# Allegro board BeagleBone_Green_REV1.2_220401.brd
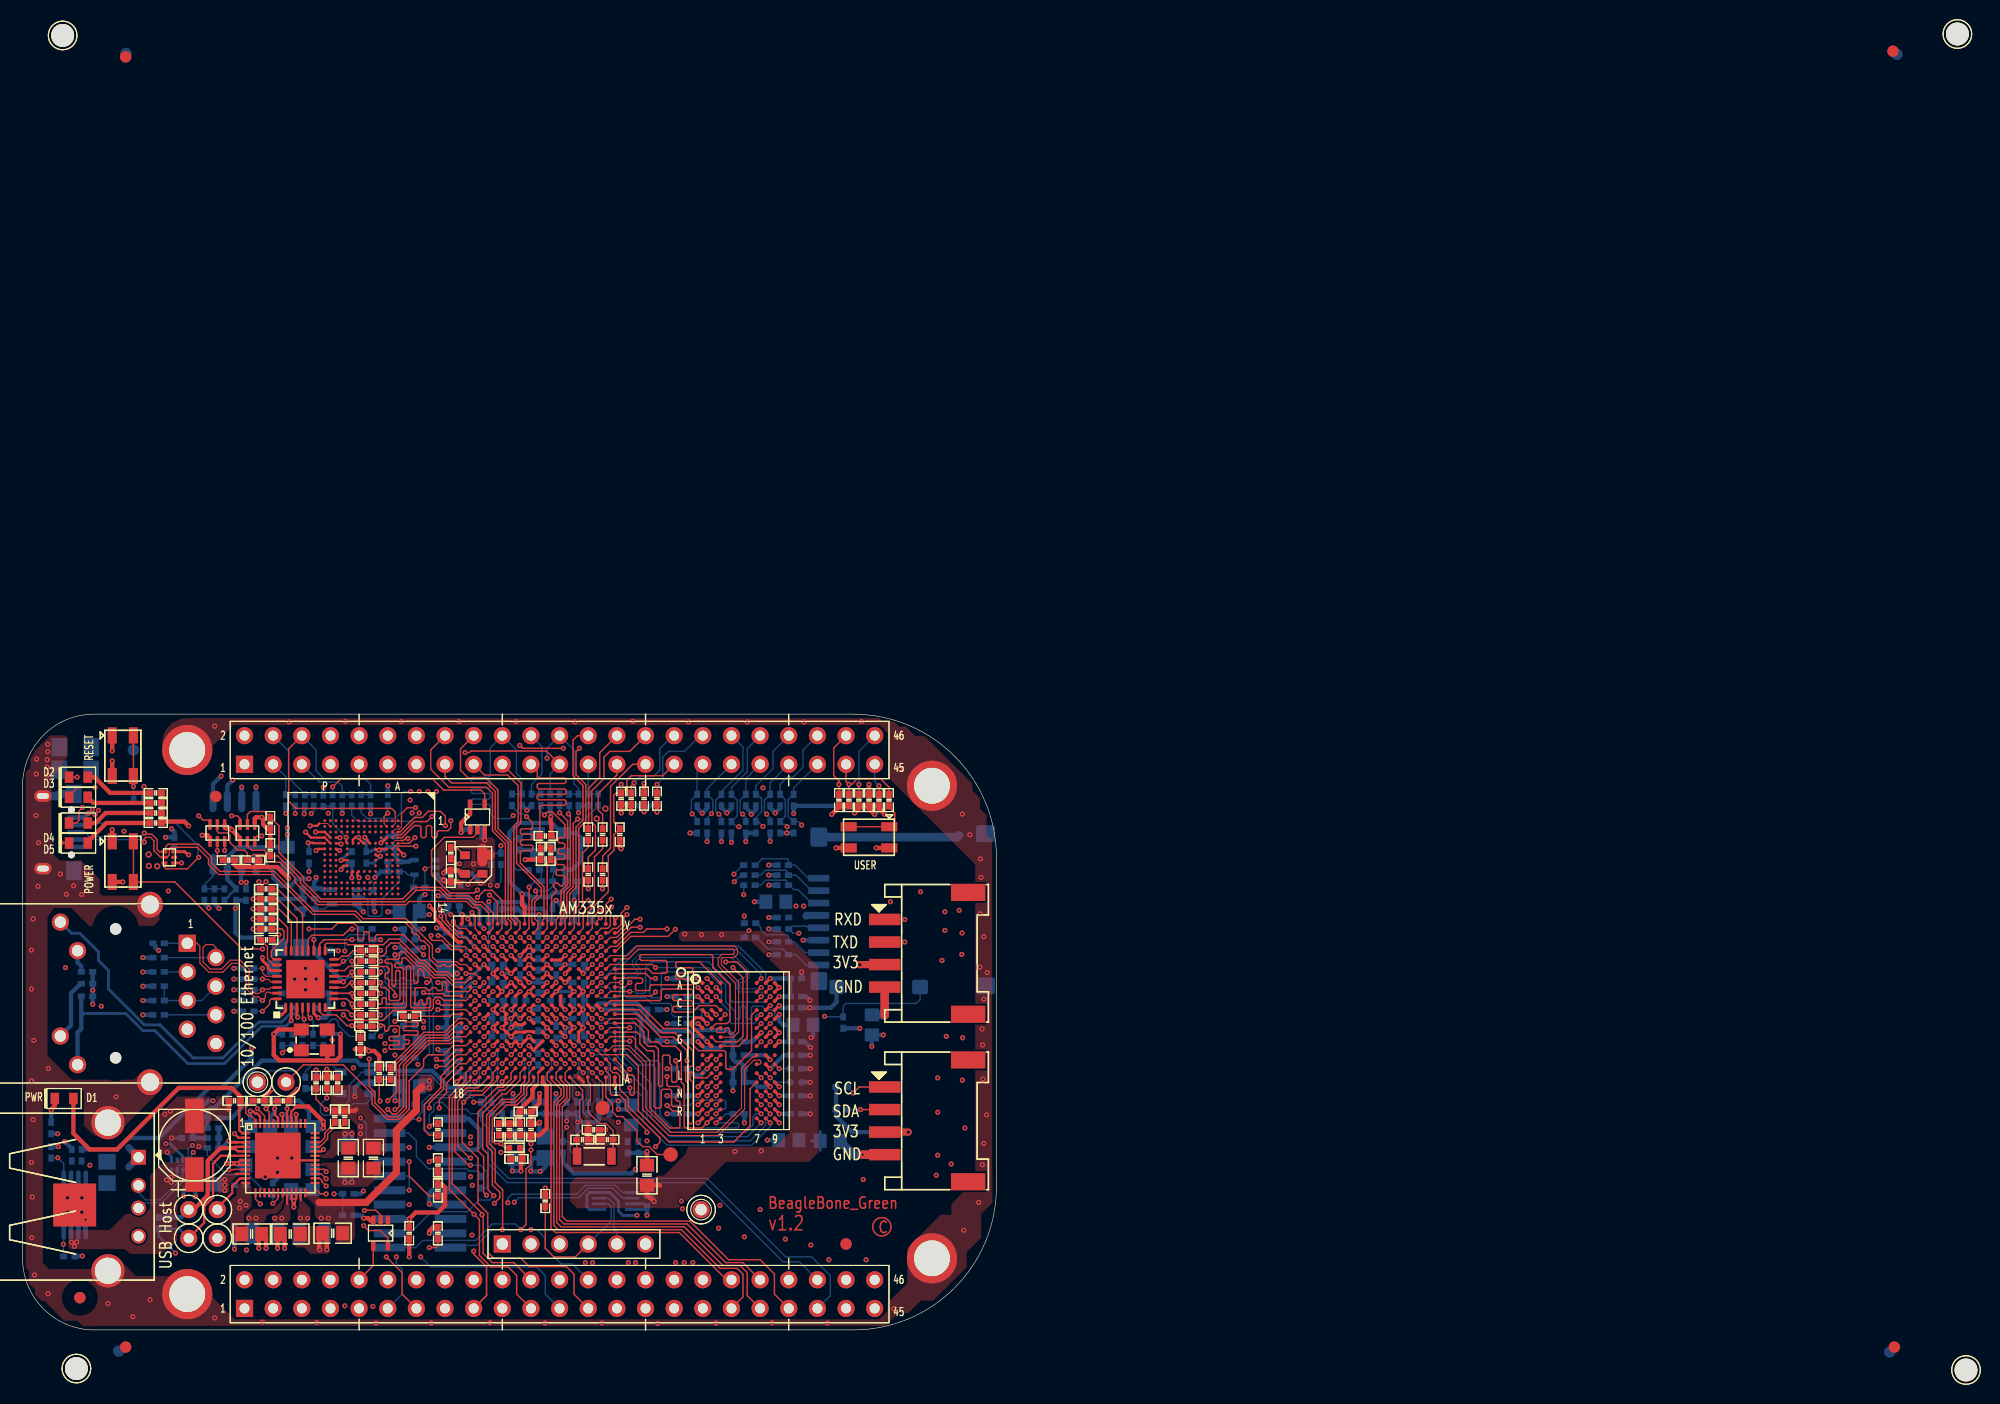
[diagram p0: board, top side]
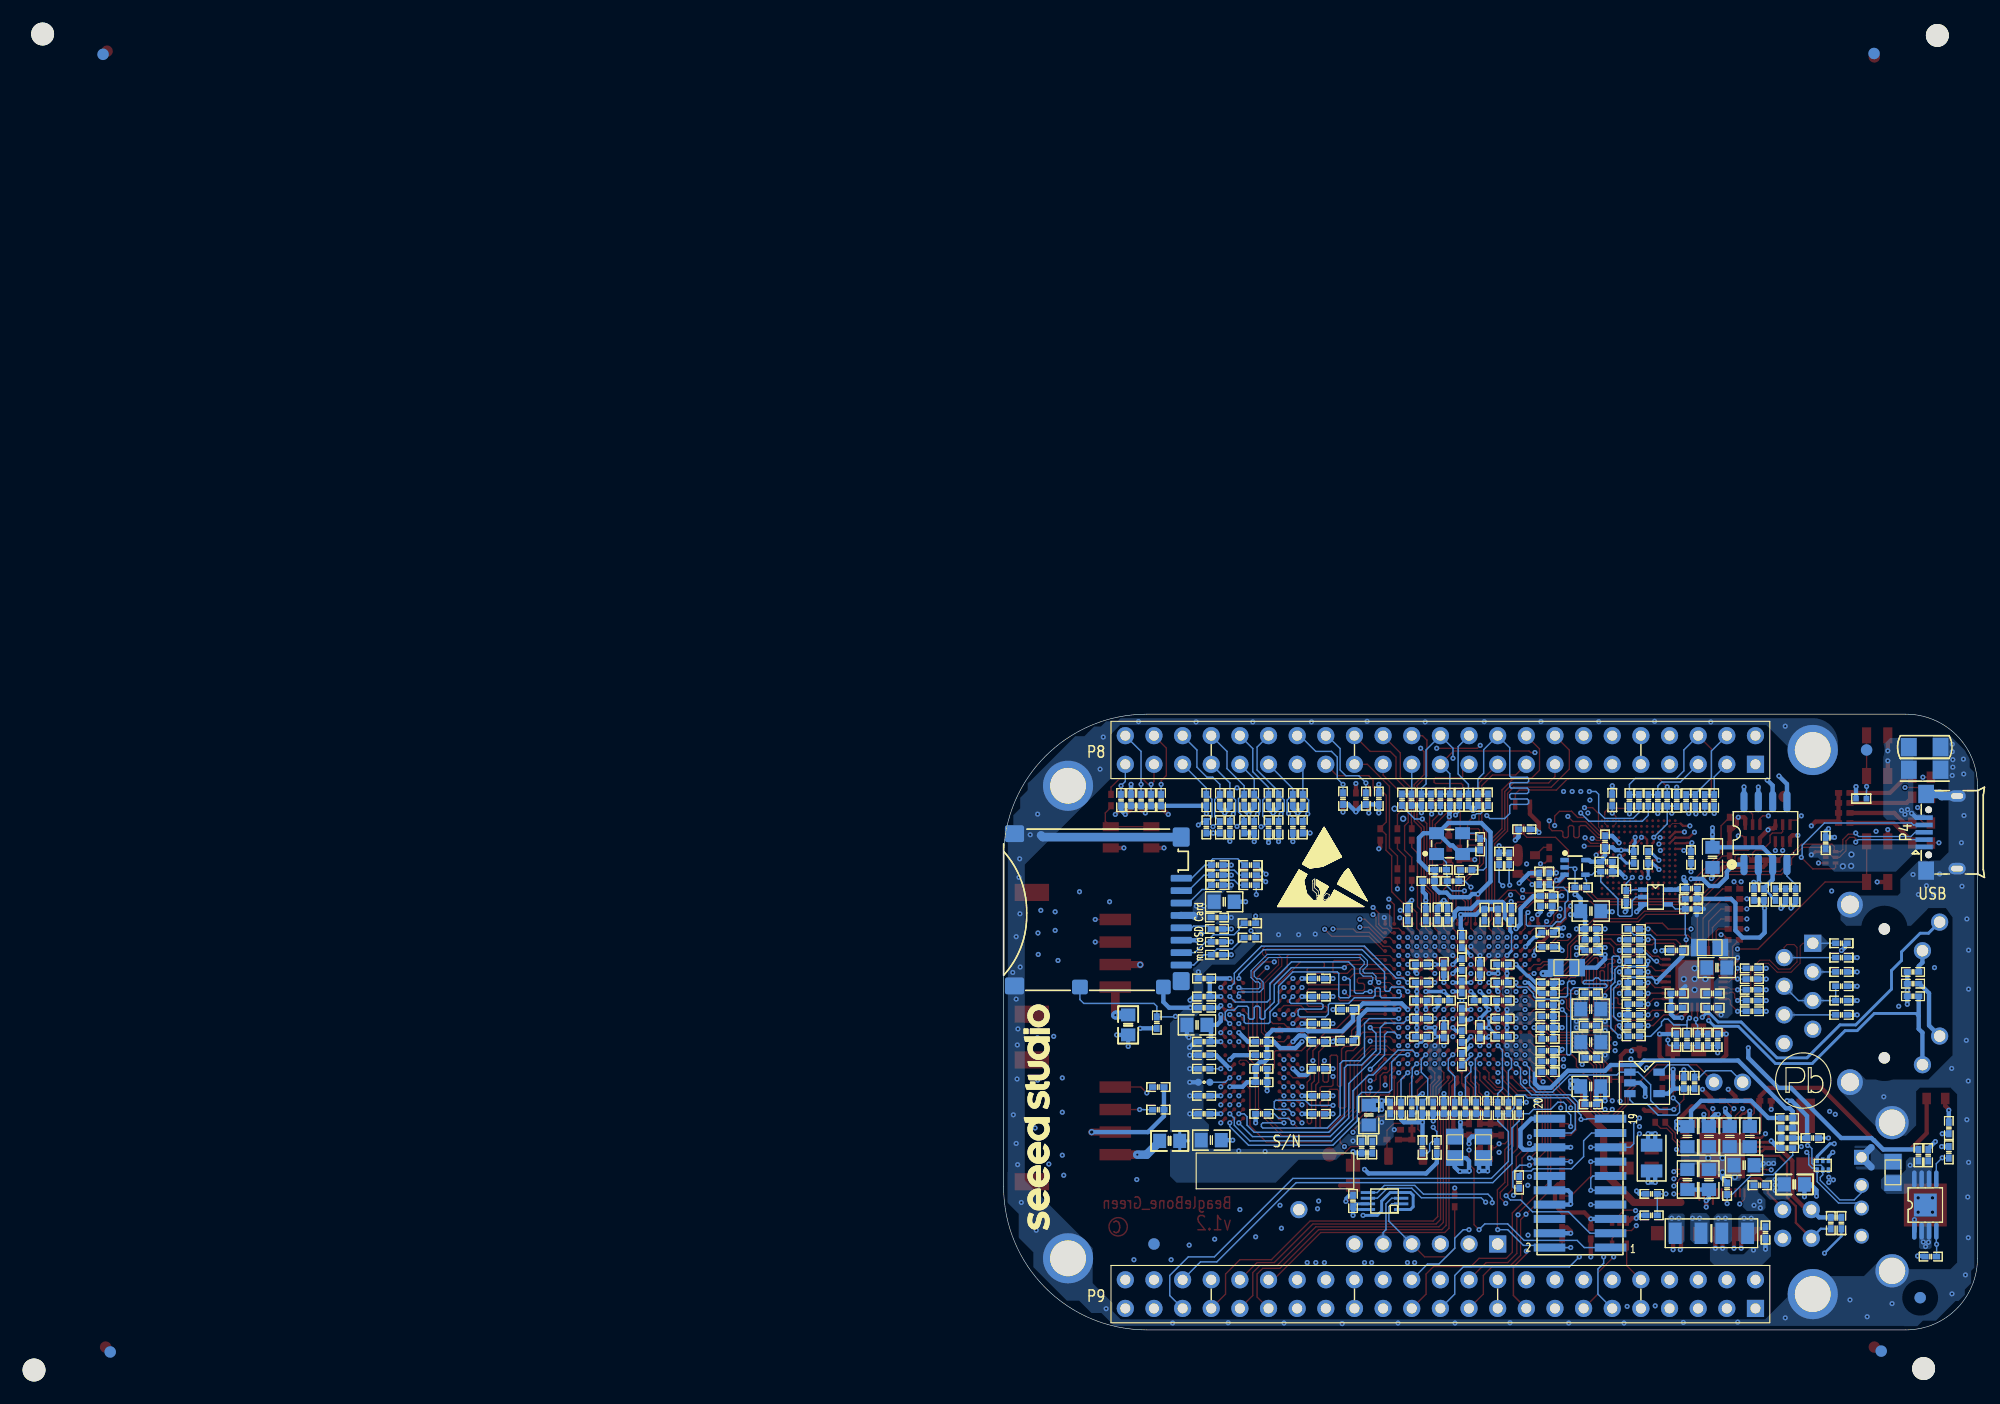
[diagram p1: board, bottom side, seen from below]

Outline 86.36 x 54.61 mm; copper layers: TOP, LYR2_GND, LYR3, LYR4, LYR5_PWR, BOTTOM. Coordinates in mm from the lower left corner of the outline.
Outline path: 0,48.26 0,6.35 arc(1.86,1.86) 6.35,0 73.66,0 arc(82.64,3.72) 86.36,12.7 86.36,41.91 arc(82.64,50.89) 73.66,54.61 6.35,54.61 arc(1.86,52.75) 0,48.26

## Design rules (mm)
constraint set DEFAULT: min track width 0.121
net group RX: nets RXN RXP
net group TX: nets TXN TXP
net group USB0: nets USB0_DM USB0_DP
net group USB1: nets USB1_DM USB1_DP
net group AM3: nets AM3_MMC1_DAT0 AM3_MMC1_DAT1 AM3_MMC1_DAT2 AM3_MMC1_DAT3 AM3_MMC1_DAT4 AM3_MMC1_DAT5 AM3_MMC1_DAT6 AM3_MMC1_DAT7 N22710186 N22710189
net group CLK: nets SD_CLK
net group DDR_ADD: nets DDR_A0 DDR_A1 DDR_A2 DDR_A3 DDR_A4 DDR_A5 DDR_A6 DDR_A7 DDR_A8 DDR_A9 DDR_A10 DDR_A11 DDR_A12 DDR_A13 DDR_A14 DDR_BA0 DDR_BA1 DDR_BA2 DDR_CASN DDR_CKE DDR_CLK DDR_CLKN DDR_CSN DDR_ODT DDR_RASN DDR_WEN
net group DDR_DQ0: nets DDR_D0 DDR_D1 DDR_D2 DDR_D3 DDR_D4 DDR_D5 DDR_D6 DDR_D7 DDR_DQM0 DDR_DQS0 DDR_DQSN0
net group DDR_DQ1: nets DDR_D8 DDR_D9 DDR_D10 DDR_D11 DDR_D12 DDR_D13 DDR_D14 DDR_D15 DDR_DQM1 DDR_DQS1 DDR_DQSN1
net group MMC1: nets MMC1_CLK MMC1_CMD MMC1_DAT0 MMC1_DAT1 MMC1_DAT2 MMC1_DAT3 MMC1_DAT4 MMC1_DAT5 MMC1_DAT6 MMC1_DAT7
nets with their own width: min track width 0.203; nets USB1_VBUS

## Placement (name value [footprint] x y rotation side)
C1  10uF,10V  [805]  20.32 8.51 180 top
C2  10uF,10V  [805]  16.23 12.9 0 bottom
C3  100nF,16V  [402]  20.95 20.32 180 top
C4  10uF,10V  [805]  20.19 17.14 90 bottom
C5  10pF  [402]  31.62 22.73 90 top
C6  10pF  [402]  45.95 42.21 270 top
C7  10uF,10V  [805]  23.81 13.34 270 bottom
C8  10uF,10V  [805]  25.72 13.34 270 bottom
C9  10uF,10V  [805]  23.75 8.51 180 top
C10  10uF,10V  [805]  20.7 14.61 180 bottom
C11  10uF,10V  [805]  28.89 15.24 270 top
C12  10uF,10V  [805]  27.5 8.57 0 top
C13  10uF,10V  [805]  23.81 17.14 90 bottom
C14  10uF,10V  [805]  25.72 17.14 90 bottom
C15  10uF,10V  [805]  21.97 17.14 90 bottom
C16  2.2uF  [402]  14.61 17.02 180 bottom
C17  2.2uF  [402]  19.81 38.61 270 bottom
C18  2.2uF  [402]  18.8 20.32 180 top
C19  470pF,50V  [402]  17.02 38.61 270 bottom
C20  100nF,16V  [402]  18.92 38.61 270 bottom
C21  18pF,50V  [402]  49.64 16.88 180 top
C22  18pF,50V  [402]  51.85 16.88 0 top
C23  100nF,16V  [0402]  25.35 39.14 180 bottom
C24  100nF,16V  [402]  43.79 15.16 0 top
C25  18pF,50V  [402]  47.6 40.82 0 bottom
C26  18pF,50V  [402]  44.09 43.08 270 bottom
C27  4.7uF  [402]  25.4 38.23 180 bottom
C28  100nF,16V  [402]  55.88 28.41 0 bottom
C29  100nF,16V  [402]  34.29 8.57 270 top
C30  100nF,16V  [402]  28.89 10.16 0 bottom
C31  100nF,16V  [402]  43.18 17.78 270 top
C32  1nF,50V  [402]  42.23 17.78 270 top
C33  100nF,16V  [402]  44.13 17.78 270 top
C34  100uF,10V  [RD205SMD_250D]  15.24 16.38 90 top
C35  100nF,16V  [402]  4.37 15.49 90 bottom
C36  100nF,16V  [402]  13.46 43.18 90 bottom
C37  100nF,16V  [402]  27.94 21.91 270 top
C38  100nF,16V  [402]  34.29 34.61 180 bottom
C39  10uF,10V  [805]  34.29 25.53 0 bottom
C40  10uF,10V  [805]  34.29 28.45 0 bottom
C41  100nF,16V  [402]  42.12 32.41 180 bottom
C42  100nF,16V  [402]  45.72 32.41 270 bottom
C43  100nF,16V  [402]  47.32 32.01 90 bottom
C44  100nF,16V  [402]  38.12 25.81 180 bottom
C45  100nF,16V  [402]  38.1 29.84 180 bottom
C46  100nF,16V  [402]  44.12 29.21 0 bottom
C47  100nF,16V  [402]  45.72 30.41 270 bottom
C48  100nF,16V  [402]  47.32 29.21 0 bottom
C49  100nF,16V  [402]  45.72 28.01 90 bottom
C50  100nF,16V  [402]  47.32 26.41 90 bottom
C51  100nF,16V  [402]  34.29 29.84 180 bottom
C52  100nF,16V  [402]  34.29 26.99 180 bottom
C53  100nF,16V  [402]  34.29 24.13 180 bottom
C54  100nF,16V  [402]  38.12 26.81 180 bottom
C55  10uF,10V  [805]  31.11 15.24 270 top
C56  100nF,16V  [402]  45.72 34.41 270 bottom
C57  100nF,16V  [402]  55.12 47.12 270 top
C58  100nF,16V  [402]  42.52 36.81 90 bottom
C59  100nF,16V  [402]  43.5 19.68 270 bottom
C60  100nF,16V  [402]  42.12 27.61 180 bottom
C61  100nF,16V  [402]  75.06 46.99 270 top
C62  10uF,10V  [805]  34.29 21.59 0 bottom
C63  100nF,16V  [402]  44.12 26.41 90 bottom
C64  100nF,16V  [402]  34.29 20 180 bottom
C65  100nF,16V  [402]  42.12 29.21 180 bottom
C66  100nF,16V  [402]  42.12 30.81 180 bottom
C67  100nF,16V  [402]  34.29 35.56 180 bottom
C68  100nF,16V  [402]  48.92 36.81 270 bottom
C69  100nF,16V  [402]  38.12 28.81 0 bottom
C70  100nF,16V  [402]  42.12 26.01 180 bottom
C71  100nF,16V  [402]  38.23 37.59 180 bottom
C72  100nF,16V  [402]  45.72 26.01 270 bottom
C73  100nF,16V  [402]  49.32 32.41 0 bottom
C74  100nF,16V  [402]  50.52 36.81 270 bottom
C75  100nF,16V  [402]  53.09 47.12 270 bottom
C76  100nF,16V  [402]  75.06 46.99 270 bottom
C77  10uF,10V  [805]  34.29 37.15 180 bottom
C78  100nF,16V  [402]  34.29 33.66 0 bottom
C79  100nF,16V  [402]  38.12 27.81 180 bottom
C80  100nF,16V  [402]  41.32 36.81 90 bottom
C81  100nF,16V  [402]  47.88 36.83 90 bottom
C82  100nF,16V  [402]  38.12 24.77 180 bottom
C83  100nF,16V  [402]  38.12 23.81 180 bottom
C84  100nF,16V  [402]  46.99 36.83 90 bottom
C85  100nF,16V  [402]  38.12 22.86 180 bottom
C86  100nF,16V  [402]  38.12 35.24 180 bottom
C87  100nF,16V  [402]  38.1 30.73 180 bottom
C88  100nF,16V  [402]  45.72 24.01 270 bottom
C89  1uF,10V  [402]  46.35 19.68 270 bottom
C90  1uF,10V  [402]  44.45 19.68 270 bottom
C91  1uF,10V  [402]  45.4 19.68 270 bottom
C92  100nF,16V  [402]  48.26 19.68 270 bottom
C93  100nF,16V  [402]  45.09 17.78 270 top
C94  100nF,16V  [402]  44.12 32.01 270 bottom
C95  10uF,10V  [805]  53.98 19.05 90 bottom
C96  10uF,10V  [805]  55.37 13.72 90 top
C97  100nF,16V  [402]  49.32 30.81 180 bottom
C98  100nF,16V  [402]  49.32 29.21 180 bottom
C99  100nF,16V  [402]  49.32 27.61 180 bottom
C100  100nF,16V  [402]  49.32 26.01 180 bottom
C101  100nF,16V  [402]  52.07 19.68 270 bottom
C102  100nF,16V  [402]  53.66 16.19 90 bottom
C103  100nF,16V  [402]  54.61 16.19 90 bottom
C104  1uF,10V  [402]  49.21 19.68 270 bottom
C105  100nF,16V  [402]  47.31 19.68 270 bottom
C106  1uF,10V  [402]  43.72 36.81 90 bottom
C107  100nF,16V  [402]  58.42 31.17 180 bottom
C108  100nF,16V  [402]  58.42 29.57 180 bottom
C109  100nF,16V  [402]  58.42 27.17 180 bottom
C110  100nF,16V  [402]  58.42 25.57 180 bottom
C111  100nF,16V  [402]  58.42 23.16 180 bottom
C112  100nF,16V  [402]  58.42 20.76 180 bottom
C113  100nF,16V  [402]  58.42 19.16 180 bottom
C114  100nF,16V  [402]  68.58 31.17 0 bottom
C115  100nF,16V  [402]  68.58 29.57 0 bottom
C116  100nF,16V  [402]  68.58 28.57 0 bottom
C117  100nF,16V  [402]  68.58 25.57 0 bottom
C118  10uF,10V  [805]  69.22 27.05 180 bottom
C119  100nF,16V  [402]  68.58 24.36 0 bottom
C120  100nF,16V  [402]  68.58 20.76 0 bottom
C121  100nF,16V  [402]  68.58 19.16 0 bottom
C122  10uF,10V  [805]  67.94 16.83 180 bottom
C123  1nF,50V  [402]  63.5 24.36 0 bottom
C124  100nF,16V  [402]  63.5 21.96 180 bottom
C125  2.2uF  [402]  32.38 46.99 90 bottom
C126  10uF,10V  [805]  23.5 41.91 90 bottom
C127  100nF,16V  [402]  25.4 41.91 270 bottom
C128  100nF,16V  [402]  29.21 41.91 90 bottom
C129  100nF,16V  [402]  30.48 41.91 270 bottom
C130  100nF,16V  [402]  33.02 43.31 90 bottom
C131  100nF,16V  [402]  23.5 28.57 0 bottom
C132  100nF,16V  [402]  23.5 29.84 0 bottom
C133  10uF,10V  [805]  23.11 32.13 180 bottom
C134  1uF,10V  [402]  26.67 28.57 180 bottom
C135  100nF,16V  [402]  26.67 33.66 0 bottom
C136  470pF,50V  [0402]  26.67 29.84 180 bottom
C137  10pF,50V  [402]  12.06 34.29 180 bottom
C138  10pF,50V  [402]  12.06 33.02 180 bottom
C139  10pF,50V  [402]  12.06 31.75 180 bottom
C140  10pF,50V  [402]  12.06 27.94 180 bottom
C141  22nF,50V  [402]  12.06 30.48 180 bottom
C142  33pF,50V  [402]  23.04 25.73 90 bottom
C143  33pF,50V  [402]  26.7 25.73 90 bottom
C144  100nF,16V  [0402]  32.89 41.53 180 bottom
C145  10pF  [402]  32.89 40.64 180 bottom
C146  100nF  [402]  22.2 12.52 90 bottom
C147  1nF  [C1206]  4.67 51.69 0 bottom
C152  100nF,16V  [402]  26.04 21.91 90 bottom
C153  10uF,10V  [805]  66.8 37.97 180 bottom
C154  100nF,16V  [402]  67.44 36.58 180 bottom
C155  100nF,16V  [402]  55.37 11.43 270 bottom
C158  100nF,16V  [402]  40.18 44.4 0 bottom
C159  100nF,16V  [402]  37.97 40.26 270 top
D1  19,217/BHC,ZL1M2RY/3T  [LED_0603]  3.68 20.52 0 top
D2  19,217/BHC,ZL1M2RY/3T  [LED_0603]  4.95 49.02 0 top
D3  19,217/BHC,ZL1M2RY/3T  [LED_0603]  4.95 47.24 0 top
D4  19,217/BHC,ZL1M2RY/3T  [LED_0603]  4.95 44.96 0 top
D5  19,217/BHC,ZL1M2RY/3T  [LED_0603]  4.95 43.18 0 top
D6  TPD1E1B04DPY  [D0402]  10.31 47.12 180 bottom
D7  TPD1E1B04DPY  [D0402]  43.63 16.15 180 top
FB1  150R,800mA  [SM-7351-IND-0805]  36.45 32.13 0 bottom
FB2  150R,800mA  [SM-7351-IND-0805]  46.35 16.19 270 bottom
FB3  150R,800mA  [SM-7351-IND-0805]  43.81 16.19 270 bottom
FB4  150R,800mA  [SM-7351-IND-0805]  23.75 33.91 180 bottom
FB7  150R,800mA  [SM-7351-IND-0805]  7.49 13.97 90 bottom
J1  Header;1*6P  [SIP6]  42.55 7.62 90 top
J4  Grove  [4P-SMD-2_0-90D]  76.45 18.54 270 top
J5  Grove  [4P-SMD-2_0-90D]  76.45 33.4 270 top
L1  2.2uH,1.3A  [2520]  21.53 8.57 180 bottom
L2  2.2uH,1.3A  [2520]  25.65 8.57 0 bottom
L3  2.2uH,1.3A  [2520]  28.89 15.24 270 bottom
MTG1  MHOLE  [MTGH200C125D_PL]  14.61 3.17 90 top
MTG2  MHOLE  [MTGH200C125D_PL]  80.64 6.35 90 top
MTG3  MHOLE  [MTGH200C125D_PL]  14.61 51.44 90 top
MTG4  MHOLE  [MTGH200C125D_PL]  80.64 48.26 90 top
NOREF  -  []  81.92 52.07 0 top
NOREF#2  -  []  86.36 39.69 0 top
NOREF#3  -  []  6.35 54.61 0 top
NOREF#4  -  [unnamed#2]  5.08 2.86 270 top
NOREF#5  -  []  0 0 0 top
NOREF#6  -  [unnamed#3]  3.56 114.81 180 top
NOREF#7  -  []  -368.3 -256.54 0 top
NOREF#8  -  [unnamed#2]  73.03 7.62 270 top
NOREF#9  -  [unnamed#3]  171.58 114.94 180 top
NOREF#10  -  []  80.64 6.35 0 top
NOREF#11  -  []  -11.96 0 90 top
NOREF#12  -  [unnamed#3]  4.78 -3.43 0 top
NOREF#13  -  [unnamed#2]  17.14 47.31 270 top
NOREF#14  -  []  0 0 0 top
NOREF#15  -  [unnamed#2]  9.14 -1.52 270 top
NOREF#16  -  []  86.36 27.94 0 top
NOREF#17  -  []  86.36 12.7 0 top
NOREF#18  -  [unnamed#3]  172.34 -3.56 0 top
NOREF#19  -  []  85.72 39.05 0 top
NOREF#20  -  []  85.72 28.57 0 top
NOREF#21  -  []  14.61 3.17 0 top
NOREF#22  -  [unnamed#2]  165.99 -1.52 270 top
NOREF#23  -  [unnamed#2]  165.86 113.41 270 top
NOREF#24  -  []  85.72 28.57 0 top
NOREF#25  -  []  80.64 48.26 0 top
NOREF#26  -  [unnamed#2]  9.14 112.9 270 top
NOREF#27  -  []  14.61 51.44 0 top
NOREF#28  -  []  80.64 6.35 0 top
NOREF#29  -  []  -368.17 -256.47 0 top
NOREF#30  -  []  14.61 3.17 0 top
NOREF#31  -  []  0 -11.96 0 top
NOREF#32  -  [unnamed#2]  9.17 113.21 90 bottom
NOREF#33  -  [unnamed#2]  166.22 113.13 90 bottom
NOREF#34  -  [unnamed#2]  8.53 -1.88 270 bottom
NOREF#35  -  [unnamed#2]  5.08 2.86 270 bottom
NOREF#36  -  []  1.91 53.34 180 bottom
NOREF#37  -  [unnamed#2]  9.83 51.44 270 bottom
NOREF#38  -  [unnamed#2]  165.58 -1.96 270 bottom
NOREF#39  -  [unnamed#2]  73.03 7.62 270 bottom
P2  Header 2x10P  [HEADER10X2_SMD]  35.24 13.02 90 bottom
P3  ST,USB,003A  [USB-003A-4P-90D]  7.57 11.81 270 top
P4  ST,USB,001G  [5P-USB-B]  4.98 44.13 90 bottom
P5  10/100M  [RJ45-7499010211A]  14.61 34.29 270 top
P8  Header;2*23P  [HEADER23X2]  19.68 50.16 0 top
P9  Header;2*23P  [HEADER23X2]  19.68 1.91 0 top
P10  YL004-030-001  [MICRO_SD_15X14_3X1_8MM]  70.61 31.26 90 bottom
Q1  DDC114YU,7,F  [SMINI6-F3-B]  19.94 44.07 180 top
Q2  DDC114YU,7,F  [SMINI6-F3-B]  17.27 44.07 180 top
R1  100K,1%  [402]  23.11 20.32 180 top
R2  33R  [402]  64.46 41.22 0 bottom
R3  1.5K,1%  [402]  26.04 21.91 270 top
R4  1.5K,1%  [402]  26.99 21.91 270 top
R5  0R,5%  [402]  16.89 17.02 180 bottom
R6  0R,5%  [402]  18.8 8.64 270 bottom
R7  0R,5%  [402]  16.89 16.13 180 bottom
R8  0R,5%  [402]  16.89 17.91 180 bottom
R9  0R,5%  [402]  16.89 18.8 0 bottom
R10  470K,1%  [402]  16.13 38.61 270 bottom
R11  280K,1%  [402]  17.91 38.61 90 bottom
R12  470R,5%  [402]  2.54 17.91 90 bottom
R13  33R  [402]  64.46 40.34 0 bottom
R14  10K,1%  [402]  28.89 12.06 180 bottom
R15  33R  [402]  64.46 39.45 0 bottom
R16  33R  [402]  32.64 22.73 270 top
R17  1M,1%  [402]  46.51 39.8 180 bottom
R18  33R,5%  [0402]  40.64 13.08 90 bottom
R19  0R,5%  [402]  41.59 19.68 270 bottom
R20  0R,5%  [402]  42.55 19.68 90 bottom
R21  33R  [402]  64.52 36.07 0 bottom
R22  49.9R,1%  [402]  55.88 25.65 180 bottom
R23  4.7K  [402]  36.83 12.38 270 top
R24  4.7K  [402]  36.83 14.61 90 top
R25  4.7K  [402]  36.83 8.57 90 top
R26  4.7K  [402]  50.16 19.68 90 bottom
R27  0R,5%  [402]  44.61 19.37 180 top
R28  33R,5%  [0402]  34.29 27.81 180 top
R29  0R,5%  [402]  48.67 39.8 180 bottom
R30  0R,5%  [402]  50.66 17.75 180 top
R31  33R  [402]  64.52 34.8 0 bottom
R32  33R  [402]  46.84 42.21 90 top
R33  33R  [402]  43.41 47.02 90 bottom
R34  10K,1%  [0402]  31.14 38.45 90 bottom
R35  10K,1%  [0402]  25.4 37.34 0 bottom
R36  0R,5%  [0402]  5.23 15.49 270 bottom
R37  33R,5%  [0402]  51.03 47.02 90 bottom
R38  33R,5%  [0402]  48.46 47.02 90 bottom
R39  33R,5%  [0402]  29.18 46.96 90 bottom
R40  33R,5%  [0402]  30.02 46.97 90 bottom
R41  33R,5%  [0402]  47.62 47.02 90 bottom
R42  33R,5%  [0402]  45.95 47.02 90 bottom
R43  33R,5%  [0402]  24.18 46.96 90 bottom
R44  33R,5%  [0402]  25.83 46.96 90 bottom
R45  22R,1%  [0402]  50.16 43.94 90 top
R46  0R,5%  [0402]  51.44 43.94 90 top
R47  0R,5%  [0402]  51.44 40.39 90 top
R48  0R,5%  [0402]  50.16 40.39 90 top
R49  0R,5%  [402]  38.1 33.97 0 bottom
R50  0R,5%  [402]  36.83 17.78 270 top
R51  0R,5%  [402]  40.64 19.68 90 bottom
R52  10K,1%  [402]  2.54 15.75 270 bottom
R53  10K,1%  [402]  4.14 6.5 0 bottom
R54  10K,1%  [402]  51.12 19.68 90 bottom
R55  100K,1%  [402]  54.23 47.12 90 bottom
R56  100K,1%  [402]  53.09 47.12 90 top
R57  100K,1%  [402]  59.82 46.99 90 bottom
R58  100K,1%  [402]  60.71 46.99 90 bottom
R59  100K,1%  [402]  56.26 47.12 90 bottom
R60  100K,1%  [402]  61.98 46.99 90 bottom
R61  100K,1%  [402]  62.87 46.99 90 bottom
R62  100K,1%  [402]  64.14 46.99 90 bottom
R63  100K,1%  [402]  65.02 46.99 90 bottom
R64  100K,1%  [402]  66.29 46.99 90 bottom
R65  100K,1%  [402]  67.18 46.99 90 bottom
R66  100K,1%  [402]  68.38 46.99 90 bottom
R67  100K,1%  [402]  72.39 46.99 90 bottom
R68  100K,1%  [402]  73.28 46.99 90 bottom
R69  100K,1%  [402]  74.17 46.99 90 bottom
R70  100K,1%  [402]  75.95 46.99 90 bottom
R71  2.2K,5%  [402]  11.81 44.96 180 top
R72  2.2K,5%  [402]  11.81 47.62 180 top
R73  2.2K,5%  [402]  11.81 46.74 180 top
R74  2.2K,5%  [402]  11.81 45.85 180 top
R75  100R,1%  [402]  76.83 46.99 270 top
R76  100K,1%  [402]  21.97 42.55 90 top
R77  100K,1%  [402]  21.97 44.96 270 top
R78  100K,1%  [402]  18.29 41.66 0 top
R79  100K,1%  [402]  20.45 41.66 0 top
R80  100K,1%  [402]  53.98 47.12 270 top
R81  100K,1%  [402]  52.96 43.94 270 top
R82  100K,1%  [402]  59.82 44.58 270 bottom
R83  100K,1%  [402]  60.71 44.58 270 bottom
R84  100K,1%  [402]  56.26 47.12 270 top
R85  100K,1%  [402]  61.98 44.58 270 bottom
R86  100K,1%  [402]  62.87 44.58 270 bottom
R87  100K,1%  [402]  64.14 44.58 270 bottom
R88  100K,1%  [402]  65.02 44.58 270 bottom
R89  100K,1%  [402]  66.29 44.58 270 bottom
R90  100K,1%  [402]  67.18 44.58 270 bottom
R91  100K,1%  [402]  68.38 44.58 270 bottom
R92  100K,1%  [402]  72.39 46.99 270 top
R93  100K,1%  [402]  73.28 46.99 270 top
R94  100K,1%  [402]  74.17 46.99 270 top
R95  100K,1%  [402]  75.95 46.99 270 top
R96  10K,1%  [402]  68.58 23.16 180 bottom
R97  1.5K,1%  [402]  63.5 19.16 180 bottom
R98  10K,1%  [402]  63.5 25.57 180 bottom
R99  240R,1%  [SM-7351-RES-0402]  68.58 21.96 180 bottom
R100  10K,1%  [402]  63.5 23.16 180 bottom
R101  10K,1%  [402]  50.19 47.02 90 bottom
R102  10K,1%  [402]  49.3 47.02 90 bottom
R103  10K,1%  [402]  28.35 46.96 90 bottom
R104  10K,1%  [402]  30.86 46.96 90 bottom
R105  10K,1%  [402]  46.79 47.02 90 bottom
R106  10K,1%  [402]  45.14 47.02 90 bottom
R107  10K,1%  [402]  23.34 46.96 90 bottom
R108  10K,1%  [402]  25.02 46.96 90 bottom
R109  10K,1%  [402]  44.3 47.02 90 bottom
R110  10K,1%  [402]  46.38 43.81 180 top
R111  10K,1%  [402]  26.67 46.94 270 bottom
R112  1.5K,1%  [402]  30.48 30.8 0 bottom
R113  1.5K,1%  [402]  30.48 33.66 0 bottom
R114  1.5K,1%  [402]  30.48 29.84 0 bottom
R115  10K,1%  [402]  30.48 31.75 0 bottom
R116  10K,1%  [402]  30.48 27.94 0 bottom
R117  10K,1%  [402]  30.48 28.89 0 bottom
R118  10K,1%  [402]  29.97 25.4 270 top
R119  1.5K,1%  [402]  30.48 33.66 180 top
R120  49.9R,1%  [402]  20 29.21 180 bottom
R121  49.9R,1%  [402]  20 30.16 180 bottom
R122  49.9R,1%  [402]  20 31.11 180 bottom
R123  49.9R,1%  [402]  20 32.07 180 bottom
R124  10R,1%  [402]  30.48 26.92 180 top
R125  100R,1%  [402]  30.48 27.94 180 top
R126  100R,1%  [402]  30.48 28.89 180 top
R127  100R,1%  [402]  30.48 29.84 180 top
R128  100R,1%  [402]  30.48 30.8 180 top
R129  100R,1%  [402]  21.62 34.59 180 top
R130  470R,5%  [402]  5.71 30.71 180 bottom
R131  100R,1%  [402]  30.48 26.99 180 bottom
R132  470R,5%  [402]  5.71 31.75 180 bottom
R133  100R,1%  [402]  30.48 31.75 180 top
R134  100R,1%  [402]  30.48 35.56 180 bottom
R135  10K,1%  [402]  5.71 29.59 0 bottom
R136  0R  [R1206]  4.67 49.68 180 bottom
R137  0R,5%  [402]  12.06 29.21 180 bottom
R138  100R,1%  [402]  30.48 32.7 180 bottom
R139  100R,1%  [402]  30.48 32.7 180 top
R140  0R,5%  [402]  30.48 26.04 180 bottom
R141  1M,1%  [402]  24.82 25.73 270 bottom
R142  0R,5%  [402]  25.76 25.73 90 bottom
R143  0R,5%  [402]  23.93 25.73 90 bottom
R144  12K,1%  [402]  20 28.26 180 bottom
R145  10K,1%  [402]  30.48 34.61 0 bottom
R146  0.1R,5%  [805]  71.63 16.76 0 bottom
R147  0.1R,5%  [805]  75.31 27.05 90 bottom
R148  0R,5%  [402]  35.18 39.24 180 bottom
R149  33R  [402]  21.59 39.12 0 top
R150  10K,1%  [402]  67.41 41.22 0 bottom
R151  10K,1%  [402]  67.41 39.45 0 bottom
R152  10K,1%  [402]  67.44 35.56 0 bottom
R153  10K,1%  [402]  67.44 34.42 0 bottom
R154  10K,1%  [402]  67.44 33.27 0 bottom
R155  10K,1%  [402]  67.41 40.34 0 bottom
R156  10K,1%  [402]  25.08 21.91 90 bottom
R157  10K,1%  [402]  72.77 27.25 270 bottom
R158  33R  [402]  21.59 38.23 0 top
R159  0R,5%  [402]  38.23 38.48 0 bottom
R160  0R,5%  [402]  42.42 41.78 90 bottom
R161  0R,5%  [402]  41.53 41.78 90 bottom
R162  0R,5%  [402]  27.51 46.96 270 bottom
R163  4.7K  [402]  47.94 16.19 90 bottom
R164  4.7K  [402]  49.21 16.19 90 bottom
R165  100K,1%  [402]  46.35 11.43 90 top
R166  33R  [402]  21.59 37.34 0 top
R167  33R,5%  [0402]  37.97 42.29 270 top
R168  0R,5%  [402]  19.3 12.83 180 bottom
R169  0R,5%  [402]  37.97 40.01 90 bottom
R170  0R,5%  [402]  38.86 40.01 90 bottom
R171  33R  [402]  21.59 36.45 0 top
R172  33R  [402]  21.59 35.56 0 top
R173  4.7K  [402]  12.06 9.47 270 bottom
R174  0R  [402]  13 9.47 90 bottom
R175  0R  [402]  28.57 18.92 90 top
R176  0R  [402]  27.69 18.92 90 top
R177  4.7K  [402]  72.64 21.54 0 bottom
R178  4.7K  [402]  72.64 19.53 0 bottom
R179  0R,5%  [402]  45.34 40.79 180 bottom
S1  SKRPABE010  [SW_4P]  8.89 50.93 270 top
S2  SKRPABE010  [SW_4P]  75.06 43.69 180 top
S3  SKRPABE010  [SW_4P]  8.89 41.53 270 top
TP1  Test Point  [TP1-8040]  60.17 10.67 0 top
TP2  Test Point  [TP60C_SMD]  57.47 15.56 0 top
TP3  Test Point  [TP60C_SMD]  51.44 19.68 0 top
TP4  Test Point  [TP1-8040]  20.83 21.97 0 top
TP5  Test Point  [TP60C33D]  14.73 10.67 0 top
TP6  Test Point  [TP60C33D]  14.73 8.13 0 top
TP7  Test Point  [TP60C33D]  17.27 10.67 0 top
TP8  Test Point  [TP60C33D]  17.27 8.13 0 top
TP9  Test Point  [TP60C33D]  23.37 21.97 0 top
U1  SN74AHC1G09DCKR  [DCK5_2P15X1P4]  28.55 38.39 270 bottom
U2  TPS65217CRSLR  [U_48_RSL]  22.86 15.24 0 top
U3  SN74LVC1G06DCKR  [DCK5_2P15X1P4]  40.34 45.49 0 top
U4  TL5209DR  [SO8-25X75]  18.8 44.07 180 bottom
U5  AM3358BZCZ100  [AM33XX_15X15]  45.72 29.21 180 top
U6  SN74AUP1T17DCKR  [SC70_5]  35.69 41.02 270 bottom
U7  24LC32AT,I/OT  [SOT23-5]  29.53 21.91 270 bottom
U8  TPS2051BDGNR  [DGN-16X60]  4.62 11.07 180 bottom
U9  TPD4S012DRYR  [U_6_DRY]  13.72 14.61 180 bottom
U10  TPD4S012DRYR  [U_6_DRY]  13.02 41.91 270 top
U12  MT41K256M16TW,107:P  [BGA96_T9_P8_9X14]  63.5 24.77 0 top
U13  MTFC4GACAJCN,1M WT  [BGA153_P14_P5_11P5X13]  30.05 41.91 270 top
U14  LAN8710A,EZC,TR  [QFN32_5X5MM_EP3P3MM]  25.08 31.11 0 top
U15  SN74LVC2G241DCUR  [U_8_DCU]  52.58 11.43 90 bottom
U16  SN74LVC1G07DCKR  [DCK5_2P15X1P4]  31.75 8.59 180 top
Y1  32.768kHz 12.5pF  [X2_SMD_3_2X1_5MM]  50.7 15.41 180 top
Y2  24MHz 18pF  [X4-SMD-3_2X2_5X1_0MM]  46.81 43.13 180 bottom
Y3  25MHz 18pF  [X4-SMD-3_2X2_5X1_0MM]  25.87 25.72 0 top
Y4  24.576MHz  [OSC4_61X65LS_79X98SMD]  40.01 41.27 90 top

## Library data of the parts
C1 C2 C4 C7-C15 C39 C40 C55 C62 C77 C95 C96 C118 C122 C126 C133 C153 = CAP_10uF_Y5V_10V_10%_0805
C3 C20 C23 C24 C28-C31 C33 C35-C38 C41-C54 C56-C61 C63-C76 C78-C88 C92-C94 C97-C103 C105 C107-C117 C119-C121 C124 C127-C132 C135 C144 C152 C154 C155 C158 C159 = CAP_0.1uF_X5R_6.3V_20% 0201
C5 C6 C16-C18 C27 C125 C137-C140 C145-C147 = CC
C19 = CAP_470PF_X7R_25V_10%_0402
C21 C22 C25 C26 = CAP_18PF_COG_50V_5%_0402
C32 C123 = CAP_0.001_X7R_50V_5%_0402
C34 = CAP_100UF_TANT_6.3V_3528-21
C89-C91 C104 C106 C134 = CAP_1.0UF_X5R_10V_10%_0402
C136 = 470pF/5%/50V/C0G/0603_0
C141 = CAP_0402_0.1uf_X5R_10V
C142 C143 = CAP_30PF_COG_50V_5%_0402
D1-D5 = LED_LTST-C150GKT_0
D6 D7 = DIODE TVS BI-DIR
FB1-FB4 FB7 = FER_180_200_0
J1 = HEADER 6: User Part Number: ***
J4 J5 = HEADER 4
L1-L3 = IND_2.2uH_2.6A_10%_SMD
MTG1-MTG4 = MHOLE
P2 = HDR_10x2_CJTAG_0
P3 = CONN_54819-0578_2
P4 = MINI-USB-AB-SOCKET
P5 = CONN_RJ45_MAG_WE_0
P8 P9 = HDR_46_F_2_0.1_0.1
P10 = MicroSD Card_10+4P
Q1 Q2 = RN1907
R1 R36 R55-R70 R75-R95 R165 = RES_100K_1/16W_1%_0402
R2 R13 R15 R16 R21 R23-R26 R31-R33 R136 R149 R158 R163 R164 R166 R171-R178 = R
R3 R4 R119 R168 = RES_1.5K_1/16W_5%_0402
R5-R9 R50 R51 R112-R118 R159-R162 R169 R170 = RES_4.75K_1/16W_1%_0402
R10 R12 R71-R74 R130 R132 = RES_470_1/10W_5%_0402
R11 = RES_470_1/10W_5%_0402: signal model: 33OHMRESISTOR1_16W5_0402_SM_735_33
R14 = RES_10K_1/16W_1%_0402: signal model: 33OHMRESISTOR1_16W5_0402_SM_735_33
R17 = RES_1M_1/16W_1%_0402: signal model: 33OHMRESISTOR1_16W5_0402_SM_735_33
R18 R47 = RES_33_0402: signal model: 33OHMRESISTOR1_16W5_0402_SM_735_33
R19 R27 R29 R30 R140 R142 R143 R148 R156 R179 = RES_0_1/16W_1%_0402
R20 = RES_0_1/16W_1%_0402: signal model: 33OHMRESISTOR1_16W5_0402_SM_735_33
R22 R120-R123 = RES_4.7K_0402
R28 R37-R46 R48 R167 = RES_33_0402
R34 R35 R52-R54 R96-R98 R100-R111 R135 R137 R145 R150-R155 R157 = RES_10K_1/16W_1%_0402
R49 = RES_100K_1/16W_1%_0402: signal model: 33OHMRESISTOR1_16W5_0402_SM_735_33
R99 = Res
R124-R126 R129 R134 R138 = 100-1/10W-1%-0603_4
R127 R128 R131 R133 R139 = RES_100_1/10W_5%_0402
R141 = RES_1M_1/16W_1%_0402
R144 = RES_12.1K_1/16W_1%_0402
R146 R147 = RES_0.1_0805
S1 S3 = SW_KT11P2JM_2
S2 = SW_KT11P2JM_1
TP1-TP9 = TESTPT1
U1 = SN74LVC1G08DCKR
U2 = PWR_TPS65217_2
U3 = IC_SN74LVC1G06DCK_0
U4 = PWR_TLV70233DBV_0: Tolerance: X; User Part Number: X
U5 = IC_AM335X_ZCZ
U6 = SN74AUP1T17DCKR
U7 = MEM_24LC32_SOT23-5
U8 = TPS2061_1: User Part Number: X; Tolerance: X
U9 U10 = PROT_TPD4S012
U12 = MT47H256M8_7
U13 = MEM_MNAND_2GB
U14 = LAN8710 QFN32_1
U15 = IC_SN74LVC2G241_1
U16 = IC_SN74LVC1G07DCK
Y1 = XTAL_2P
Y2 Y3 = XTAL_4P
Y4 = OSC_12MHz_1.3V: Tolerance: TOL*; User Part Number: P/N*

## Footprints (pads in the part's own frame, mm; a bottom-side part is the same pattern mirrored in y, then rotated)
4P-SMD-2_0-90D
  rect 1.524x3.048 smd: (-5.4,7.4) (5.4,7.4)
  rect 1.016x2.794 smd: 1(-3,0) 2(-1,0) 3(1,0) 4(3,0)
5P-USB-B
  round 0.61 hole 0.61 unplated: (-2,-0.65) (2,-0.65)
  rect 0.406x1.524 smd: 1(-1.3,-0.25) 2(-0.65,-0.25) 3(0,-0.25) 4(0.65,-0.25) 5(1.3,-0.25)
  rect 1.626x1.397 smd: 6(3.4,-0.427) 7(-3.4,-0.427)
  oval 1.016x1.524 hole 0.508x1.067: 8(-3.22,-3.175) 9(3.22,-3.175)
402
  rect 0.635x0.508 smd: 1(-0.508,0) 2(0.508,0)
0402
  rect 0.635x0.508 smd: 1(-0.508,0) 2(0.508,0)
805
  rect 1.143x1.27 smd: 1(-0.889,0) 2(0.889,0)
2520
  rect 1.143x1.905 smd: 1(-1.143,0) 2(1.143,0)
AM33XX_15X15
  round 0.356 smd: A1(-6.8,6.8) A2(-6,6.8) A3(-5.2,6.8) A4(-4.4,6.8) A5(-3.6,6.8) A6(-2.8,6.8) A7(-2,6.8) A8(-1.2,6.8) A9(-0.4,6.8) A10(0.4,6.8) A11(1.2,6.8) A12(2,6.8) A13(2.8,6.8) A14(3.6,6.8) A15(4.4,6.8) A16(5.2,6.8) A17(6,6.8) A18(6.8,6.8) B1(-6.8,6) B2(-6,6) B3(-5.2,6) B4(-4.4,6) B5(-3.6,6) B6(-2.8,6) B7(-2,6) B8(-1.2,6) B9(-0.4,6) B10(0.4,6) B11(1.2,6) B12(2,6) B13(2.8,6) B14(3.6,6) B15(4.4,6) B16(5.2,6) B17(6,6) B18(6.8,6) C1(-6.8,5.2) C2(-6,5.2) C3(-5.2,5.2) C4(-4.4,5.2) C5(-3.6,5.2) C6(-2.8,5.2) C7(-2,5.2) C8(-1.2,5.2) C9(-0.4,5.2) C10(0.4,5.2) C11(1.2,5.2) C12(2,5.2) C13(2.8,5.2) C14(3.6,5.2) C15(4.4,5.2) C16(5.2,5.2) C17(6,5.2) C18(6.8,5.2) D1(-6.8,4.4) D2(-6,4.4) D3(-5.2,4.4) D4(-4.4,4.4) D5(-3.6,4.4) D6(-2.8,4.4) D7(-2,4.4) D8(-1.2,4.4) D9(-0.4,4.4) D10(0.4,4.4) D11(1.2,4.4) D12(2,4.4) D13(2.8,4.4) D14(3.6,4.4) D15(4.4,4.4) D16(5.2,4.4) D17(6,4.4) D18(6.8,4.4) E1(-6.8,3.6) E2(-6,3.6) E3(-5.2,3.6) E4(-4.4,3.6) E5(-3.6,3.6) E6(-2.8,3.6) E7(-2,3.6) E8(-1.2,3.6) E9(-0.4,3.6) E10(0.4,3.6) E11(1.2,3.6) E12(2,3.6) E13(2.8,3.6) E14(3.6,3.6) E15(4.4,3.6) E16(5.2,3.6) E17(6,3.6) E18(6.8,3.6) F1(-6.8,2.8) F2(-6,2.8) F3(-5.2,2.8) F4(-4.4,2.8) F5(-3.6,2.8) F6(-2.8,2.8) F7(-2,2.8) F8(-1.2,2.8) F9(-0.4,2.8) F10(0.4,2.8) F11(1.2,2.8) F12(2,2.8) F13(2.8,2.8) F14(3.6,2.8) F15(4.4,2.8) F16(5.2,2.8) F17(6,2.8) F18(6.8,2.8) G1(-6.8,2) G2(-6,2) G3(-5.2,2) G4(-4.4,2) G5(-3.6,2) G6(-2.8,2) G7(-2,2) G8(-1.2,2) G9(-0.4,2) G10(0.4,2) G11(1.2,2) G12(2,2) G13(2.8,2) G14(3.6,2) G15(4.4,2) G16(5.2,2) G17(6,2) G18(6.8,2) H1(-6.8,1.2) H2(-6,1.2) H3(-5.2,1.2) H4(-4.4,1.2) H5(-3.6,1.2) H6(-2.8,1.2) H7(-2,1.2) H8(-1.2,1.2) H9(-0.4,1.2) H10(0.4,1.2) H11(1.2,1.2) H12(2,1.2) H13(2.8,1.2) H14(3.6,1.2) H15(4.4,1.2) H16(5.2,1.2) H17(6,1.2) H18(6.8,1.2) J1(-6.8,0.4) J2(-6,0.4) J3(-5.2,0.4) J4(-4.4,0.4) J5(-3.6,0.4) J6(-2.8,0.4) J7(-2,0.4) J8(-1.2,0.4) J9(-0.4,0.4) J10(0.4,0.4) J11(1.2,0.4) J12(2,0.4) J13(2.8,0.4) J14(3.6,0.4) J15(4.4,0.4) J16(5.2,0.4) J17(6,0.4) J18(6.8,0.4) K1(-6.8,-0.4) K2(-6,-0.4) K3(-5.2,-0.4) K4(-4.4,-0.4) K5(-3.6,-0.4) K6(-2.8,-0.4) K7(-2,-0.4) K8(-1.2,-0.4) K9(-0.4,-0.4) K10(0.4,-0.4) K11(1.2,-0.4) K12(2,-0.4) K13(2.8,-0.4) K14(3.6,-0.4) K15(4.4,-0.4) K16(5.2,-0.4) K17(6,-0.4) K18(6.8,-0.4) L1(-6.8,-1.2) L2(-6,-1.2) L3(-5.2,-1.2) L4(-4.4,-1.2) L5(-3.6,-1.2) L6(-2.8,-1.2) L7(-2,-1.2) L8(-1.2,-1.2) L9(-0.4,-1.2) L10(0.4,-1.2) L11(1.2,-1.2) L12(2,-1.2) L13(2.8,-1.2) L14(3.6,-1.2) L15(4.4,-1.2) L16(5.2,-1.2) L17(6,-1.2) L18(6.8,-1.2) M1(-6.8,-2) M2(-6,-2) M3(-5.2,-2) M4(-4.4,-2) M5(-3.6,-2) M6(-2.8,-2) M7(-2,-2) M8(-1.2,-2) M9(-0.4,-2) M10(0.4,-2) M11(1.2,-2) M12(2,-2) M13(2.8,-2) M14(3.6,-2) M15(4.4,-2) M16(5.2,-2) M17(6,-2) M18(6.8,-2) N1(-6.8,-2.8) N2(-6,-2.8) N3(-5.2,-2.8) N4(-4.4,-2.8) N5(-3.6,-2.8) N6(-2.8,-2.8) N7(-2,-2.8) N8(-1.2,-2.8) N9(-0.4,-2.8) N10(0.4,-2.8) N11(1.2,-2.8) N12(2,-2.8) N13(2.8,-2.8) N14(3.6,-2.8) N15(4.4,-2.8) N16(5.2,-2.8) N17(6,-2.8) N18(6.8,-2.8) P1(-6.8,-3.6) P2(-6,-3.6) P3(-5.2,-3.6) P4(-4.4,-3.6) P5(-3.6,-3.6) P6(-2.8,-3.6) P7(-2,-3.6) P8(-1.2,-3.6) P9(-0.4,-3.6) P10(0.4,-3.6) P11(1.2,-3.6) P12(2,-3.6) P13(2.8,-3.6) P14(3.6,-3.6) P15(4.4,-3.6) P16(5.2,-3.6) P17(6,-3.6) P18(6.8,-3.6) R1(-6.8,-4.4) R2(-6,-4.4) R3(-5.2,-4.4) R4(-4.4,-4.4) R5(-3.6,-4.4) R6(-2.8,-4.4) R7(-2,-4.4) R8(-1.2,-4.4) R9(-0.4,-4.4) R10(0.4,-4.4) R11(1.2,-4.4) R12(2,-4.4) R13(2.8,-4.4) R14(3.6,-4.4) R15(4.4,-4.4) R16(5.2,-4.4) R17(6,-4.4) R18(6.8,-4.4) T1(-6.8,-5.2) T2(-6,-5.2) T3(-5.2,-5.2) T4(-4.4,-5.2) T5(-3.6,-5.2) T6(-2.8,-5.2) T7(-2,-5.2) T8(-1.2,-5.2) T9(-0.4,-5.2) T10(0.4,-5.2) T11(1.2,-5.2) T12(2,-5.2) T13(2.8,-5.2) T14(3.6,-5.2) T15(4.4,-5.2) T16(5.2,-5.2) T17(6,-5.2) T18(6.8,-5.2) U1(-6.8,-6) U2(-6,-6) U3(-5.2,-6) U4(-4.4,-6) U5(-3.6,-6) U6(-2.8,-6) U7(-2,-6) U8(-1.2,-6) U9(-0.4,-6) U10(0.4,-6) U11(1.2,-6) U12(2,-6) U13(2.8,-6) U14(3.6,-6) U15(4.4,-6) U16(5.2,-6) U17(6,-6) U18(6.8,-6) V1(-6.8,-6.8) V2(-6,-6.8) V3(-5.2,-6.8) V4(-4.4,-6.8) V5(-3.6,-6.8) V6(-2.8,-6.8) V7(-2,-6.8) V8(-1.2,-6.8) V9(-0.4,-6.8) V10(0.4,-6.8) V11(1.2,-6.8) V12(2,-6.8) V13(2.8,-6.8) V14(3.6,-6.8) V15(4.4,-6.8) V16(5.2,-6.8) V17(6,-6.8) V18(6.8,-6.8)
BGA96_T9_P8_9X14
  round 0.356 smd: A1(-3.2,6.001) A2(-2.4,6.001) A3(-1.6,6.001) A7(1.6,6.001) A8(2.4,6.001) A9(3.2,6.001) B1(-3.2,5.201) B2(-2.4,5.201) B3(-1.6,5.201) B7(1.6,5.201) B8(2.4,5.201) B9(3.2,5.201) C1(-3.2,4.401) C2(-2.4,4.401) C3(-1.6,4.401) C7(1.6,4.401) C8(2.4,4.401) C9(3.2,4.401) D1(-3.2,3.6) D2(-2.4,3.6) D3(-1.6,3.6) D7(1.6,3.6) D8(2.4,3.6) D9(3.2,3.6) E1(-3.2,2.8) E2(-2.4,2.8) E3(-1.6,2.8) E7(1.6,2.8) E8(2.4,2.8) E9(3.2,2.8) F1(-3.2,2) F2(-2.4,2) F3(-1.6,2) F7(1.6,2) F8(2.4,2) F9(3.2,2) G1(-3.2,1.2) G2(-2.4,1.2) G3(-1.6,1.2) G7(1.6,1.2) G8(2.4,1.2) G9(3.2,1.2) H1(-3.2,0.4) H2(-2.4,0.4) H3(-1.6,0.4) H7(1.6,0.4) H8(2.4,0.4) H9(3.2,0.4) J1(-3.2,-0.4) J2(-2.4,-0.4) J3(-1.6,-0.4) J7(1.6,-0.4) J8(2.4,-0.4) J9(3.2,-0.4) K1(-3.2,-1.2) K2(-2.4,-1.2) K3(-1.6,-1.2) K7(1.6,-1.2) K8(2.4,-1.2) K9(3.2,-1.2) L1(-3.2,-2) L2(-2.4,-2) L3(-1.6,-2) L7(1.6,-2) L8(2.4,-2) L9(3.2,-2) M1(-3.2,-2.8) M2(-2.4,-2.8) M3(-1.6,-2.8) M7(1.6,-2.8) M8(2.4,-2.8) M9(3.2,-2.8) N1(-3.2,-3.6) N2(-2.4,-3.6) N3(-1.6,-3.6) N7(1.6,-3.6) N8(2.4,-3.6) N9(3.2,-3.6) P1(-3.2,-4.401) P2(-2.4,-4.401) P3(-1.6,-4.401) P7(1.6,-4.401) P8(2.4,-4.401) P9(3.2,-4.401) R1(-3.2,-5.201) R2(-2.4,-5.201) R3(-1.6,-5.201) R7(1.6,-5.201) R8(2.4,-5.201) R9(3.2,-5.201) T1(-3.2,-6.001) T2(-2.4,-6.001) T3(-1.6,-6.001) T7(1.6,-6.001) T8(2.4,-6.001) T9(3.2,-6.001)
BGA153_P14_P5_11P5X13
  round 0.254 smd: A1(-3.25,3.25) A2(-2.75,3.25) A3(-2.25,3.25) A4(-1.75,3.25) A5(-1.25,3.25) A6(-0.75,3.25) A7(-0.25,3.25) A8(0.25,3.25) A9(0.75,3.25) A10(1.25,3.25) A11(1.75,3.25) A12(2.25,3.25) A13(2.75,3.25) A14(3.25,3.25) B1(-3.25,2.75) B2(-2.75,2.75) B3(-2.25,2.75) B4(-1.75,2.75) B5(-1.25,2.75) B6(-0.75,2.75) B7(-0.25,2.75) B8(0.25,2.75) B9(0.75,2.75) B10(1.25,2.75) B11(1.75,2.75) B12(2.25,2.75) B13(2.75,2.75) B14(3.25,2.75) C1(-3.25,2.25) C2(-2.75,2.25) C3(-2.25,2.25) C4(-1.75,2.25) C5(-1.25,2.25) C6(-0.75,2.25) C7(-0.25,2.25) C8(0.25,2.25) C9(0.75,2.25) C10(1.25,2.25) C11(1.75,2.25) C12(2.25,2.25) C13(2.75,2.25) C14(3.25,2.25) D1(-3.25,1.75) D2(-2.75,1.75) D3(-2.25,1.75) D4(-1.75,1.75) D12(2.25,1.75) D13(2.75,1.75) D14(3.25,1.75) E1(-3.25,1.25) E2(-2.75,1.25) E3(-2.25,1.25) E5(-1.25,1.25) E6(-0.75,1.25) E7(-0.25,1.25) E8(0.25,1.25) E9(0.75,1.25) E10(1.25,1.25) E12(2.25,1.25) E13(2.75,1.25) E14(3.25,1.25) F1(-3.25,0.75) F2(-2.75,0.75) F3(-2.25,0.75) F5(-1.25,0.75) F10(1.25,0.75) F12(2.25,0.75) F13(2.75,0.75) F14(3.25,0.75) G1(-3.25,0.25) G2(-2.75,0.25) G3(-2.25,0.25) G5(-1.25,0.25) G10(1.25,0.25) G12(2.25,0.25) G13(2.75,0.25) G14(3.25,0.25) H1(-3.25,-0.25) H2(-2.75,-0.25) H3(-2.25,-0.25) H5(-1.25,-0.25) H10(1.25,-0.25) H12(2.25,-0.25) H13(2.75,-0.25) H14(3.25,-0.25) J1(-3.25,-0.75) J2(-2.75,-0.75) J3(-2.25,-0.75) J5(-1.25,-0.75) J10(1.25,-0.75) J12(2.25,-0.75) J13(2.75,-0.75) J14(3.25,-0.75) K1(-3.25,-1.25) K2(-2.75,-1.25) K3(-2.25,-1.25) K5(-1.25,-1.25) K6(-0.75,-1.25) K7(-0.25,-1.25) K8(0.25,-1.25) K9(0.75,-1.25) K10(1.25,-1.25) K12(2.25,-1.25) K13(2.75,-1.25) K14(3.25,-1.25) L1(-3.25,-1.75) L2(-2.75,-1.75) L3(-2.25,-1.75) L12(2.25,-1.75) L13(2.75,-1.75) L14(3.25,-1.75) M1(-3.25,-2.25) M2(-2.75,-2.25) M3(-2.25,-2.25) M4(-1.75,-2.25) M5(-1.25,-2.25) M6(-0.75,-2.25) M7(-0.25,-2.25) M8(0.25,-2.25) M9(0.75,-2.25) M10(1.25,-2.25) M11(1.75,-2.25) M12(2.25,-2.25) M13(2.75,-2.25) M14(3.25,-2.25) N1(-3.25,-2.75) N2(-2.75,-2.75) N3(-2.25,-2.75) N4(-1.75,-2.75) N5(-1.25,-2.75) N6(-0.75,-2.75) N7(-0.25,-2.75) N8(0.25,-2.75) N9(0.75,-2.75) N10(1.25,-2.75) N11(1.75,-2.75) N12(2.25,-2.75) N13(2.75,-2.75) N14(3.25,-2.75) P1(-3.25,-3.25) P2(-2.75,-3.25) P3(-2.25,-3.25) P4(-1.75,-3.25) P5(-1.25,-3.25) P6(-0.75,-3.25) P7(-0.25,-3.25) P8(0.25,-3.25) P9(0.75,-3.25) P10(1.25,-3.25) P11(1.75,-3.25) P12(2.25,-3.25) P13(2.75,-3.25) P14(3.25,-3.25)
C1206
  rect 1.397x1.626 smd: 1(-1.41,0) 2(1.41,0)
D0402
  rrect 0.5x0.5 smd: 1(-0.463,0) 2(0.463,0)
DCK5_2P15X1P4
  rect 0.4x0.9 smd: 1(-0.65,-1.1) 2(0,-1.1) 3(0.65,-1.1) 4(0.65,1.1) 5(-0.65,1.1)
DGN-16X60
  oval 0.406x1.524 smd: 1(-0.975,-2.311) 2(-0.325,-2.311) 3(0.325,-2.311) 4(0.975,-2.311) 5(0.975,2.311) 6(0.325,2.311) 7(-0.325,2.311) 8(-0.975,2.311)
  rect 2.032x2.032 smd: 9(0,0)
HEADER10X2_SMD
  rect 0.711x2.794 smd: 1(-5.715,-2.705) 2(-5.715,2.705) 3(-4.445,-2.705) 4(-4.445,2.705) 5(-3.175,-2.705) 6(-3.175,2.705) 7(-1.905,-2.705) 8(-1.905,2.705) 9(-0.635,-2.705) 10(-0.635,2.705) 11(0.635,-2.705) 12(0.635,2.705) 13(1.905,-2.705) 14(1.905,2.705) 15(3.175,-2.705) 16(3.175,2.705) 17(4.445,-2.705) 18(4.445,2.705) 19(5.715,-2.705) 20(5.715,2.705)
HEADER23X2
  rect 1.524x1.524 hole 0.889: 1(0,0)
  round 1.524 hole 0.889: 2(0,2.54) 3(2.54,0) 4(2.54,2.54) 5(5.08,0) 6(5.08,2.54) 7(7.62,0) 8(7.62,2.54) 9(10.16,0) 10(10.16,2.54) 11(12.7,0) 12(12.7,2.54) 13(15.24,0) 14(15.24,2.54) 15(17.78,0) 16(17.78,2.54) 17(20.32,0) 18(20.32,2.54) 19(22.86,0) 20(22.86,2.54) 21(25.4,0) 22(25.4,2.54) 23(27.94,0) 24(27.94,2.54) 25(30.48,0) 26(30.48,2.54) 27(33.02,0) 28(33.02,2.54) 29(35.56,0) 30(35.56,2.54) 31(38.1,0) 32(38.1,2.54) 33(40.64,0) 34(40.64,2.54) 35(43.18,0) 36(43.18,2.54) 37(45.72,0) 38(45.72,2.54) 39(48.26,0) 40(48.26,2.54) 41(50.8,0) 42(50.8,2.54) 43(53.34,0) 44(53.34,2.54) 45(55.88,0) 46(55.88,2.54)
LED_0603
  rect 0.762x1.016 smd: 1(-0.826,0) 2(0.826,0)
MICRO_SD_15X14_3X1_8MM
  rrect 0.6x1.88 smd: 1(8.8,-0.01) 2(7.7,-0.01) 3(6.6,-0.01) 4(5.5,-0.01) 5(4.4,-0.01) 6(3.3,-0.01) 7(2.2,-0.01) 8(1.1,-0.01)
  rrect 1.3x1.3 smd: 9(-0.85,1.58)
  rrect 1.3x1.4 smd: 10(-0.85,8.98)
  rrect 1.7x1.5 smd: S1(12.45,0)
  rrect 1.6x1.5 smd: S2(-0.325,0)
  rrect 1.5x1.7 smd: S3(-0.75,14.78) S4(12.75,14.78)
MTGH200C125D_PL
  round 4.445 hole 3.175: 1(0,0)
OSC4_61X65LS_79X98SMD
  rect 0.711x0.889 smd: 1(-0.826,-0.775) 2(0.826,-0.775) 3(0.826,0.775) 4(-0.826,0.775)
QFN32_5X5MM_EP3P3MM
  oval 0.254x0.838 smd: 1(-1.751,-2.515) 8(1.751,-2.515) 17(1.751,2.515) 24(-1.751,2.515)
  rect 0.254x0.838 smd: 2(-1.251,-2.515) 3(-0.751,-2.515) 4(-0.25,-2.515) 5(0.25,-2.515) 6(0.751,-2.515) 7(1.251,-2.515) 18(1.251,2.515) 19(0.751,2.515) 20(0.25,2.515) 21(-0.25,2.515) 22(-0.751,2.515) 23(-1.251,2.515)
  oval 0.838x0.254 smd: 9(2.515,-1.751) 16(2.515,1.751) 25(-2.515,1.751) 32(-2.515,-1.751)
  rect 0.838x0.254 smd: 10(2.515,-1.251) 11(2.515,-0.751) 12(2.515,-0.25) 13(2.515,0.25) 14(2.515,0.751) 15(2.515,1.251) 26(-2.515,1.251) 27(-2.515,0.751) 28(-2.515,0.25) 29(-2.515,-0.25) 30(-2.515,-0.751) 31(-2.515,-1.251)
  rect 3.404x3.404 smd: 33(0,0)
R1206
  rect 1.397x1.626 smd: 1(-1.41,0) 2(1.41,0)
RD205SMD_250D
  rect 3.048x1.651 smd: 1(-2.603,0) 2(2.603,0)
RJ45-7499010211A
  round 1.016 hole 3.251 unplated: (-1.27,-6.35) (10.16,-6.35)
  rect 1.524x1.524 hole 1.016: 1(0,0)
  round 1.524 hole 1.016: 2(1.27,2.54) 3(2.54,0) 4(3.81,2.54) 5(5.08,0) 6(6.35,2.54) 7(7.62,0) 8(8.89,2.54) 9(-1.88,-11.252) 10(0.66,-9.728) 11(8.23,-11.252) 12(10.77,-9.728)
  round 2.286 hole 1.6: 13(-3.429,-3.302) 14(12.319,-3.302)
SC70_5
  rrect 0.4x0.75 smd: 1(-0.65,-0.925) 2(0,-0.925) 3(0.65,-0.925) 4(0.65,0.925) 5(-0.65,0.925)
SIP6
  rect 1.524x1.524 hole 1.016: 1(0,0)
  round 1.524 hole 1.016: 2(0,-2.54) 3(0,-5.08) 4(0,-7.62) 5(0,-10.16) 6(0,-12.7)
SM-7351-IND-0805
  rect 1.397x1.549 smd: 1(-0.95,0) 2(0.95,0)
SM-7351-RES-0402
  round 0.635 smd: 1(-0.508,0) 2(0.508,0)
SMINI6-F3-B
  rect 0.305x0.95 smd: 1(0.65,0.75) 2(0,0.75) 3(-0.65,0.75) 4(-0.65,-0.75) 5(0,-0.75) 6(0.65,-0.75)
SO8-25X75
  oval 0.635x1.905 smd: 1(-1.905,-2.794) 2(-0.635,-2.794) 3(0.635,-2.794) 4(1.905,-2.794) 5(1.905,2.794) 6(0.635,2.794) 7(-0.635,2.794) 8(-1.905,2.794)
SOT23-5
  rect 0.635x1.016 smd: 1(-0.953,-1.295) 2(0,-1.295) 3(0.953,-1.295) 4(0.953,1.295) 5(-0.953,1.295)
SW_4P
  rect 1.422x0.813 smd: 1(-1.8,-0.94) 2(-1.8,0.94) 3(1.8,-0.94) 4(1.8,0.94)
TP1-8040
  round 1.524 hole 1.016: 1(0,0)
TP60C33D
  round 1.524 hole 0.889: 1(0,0)
TP60C_SMD
  round 1.27 smd: 1(0,0)
U_6_DRY
  rect 0.305x0.508 smd: 1(-0.5,-0.439) 2(0,-0.439) 3(0.5,-0.439) 4(0.5,0.439) 5(0,0.439) 6(-0.5,0.439)
U_8_DCU
  rect 0.254x1.27 smd: 1(-0.749,-1.473) 2(-0.249,-1.473) 3(0.249,-1.473) 4(0.749,-1.473) 5(0.749,1.473) 6(0.249,1.473) 7(-0.249,1.473) 8(-0.749,1.473)
U_48_RSL
  rect 0.8x0.2 smd: 1(-3.075,2.2) 2(-3.075,1.8) 3(-3.075,1.4) 4(-3.075,1) 5(-3.075,0.6) 6(-3.075,0.2) 7(-3.075,-0.2) 8(-3.075,-0.6) 9(-3.075,-1) 10(-3.075,-1.4) 11(-3.075,-1.8) 12(-3.075,-2.2) 25(3.075,-2.2) 26(3.075,-1.8) 27(3.075,-1.4) 28(3.075,-1) 29(3.075,-0.6) 30(3.075,-0.2) 31(3.075,0.2) 32(3.075,0.6) 33(3.075,1) 34(3.075,1.4) 35(3.075,1.8) 36(3.075,2.2)
  rect 0.2x0.8 smd: 13(-2.2,-3.075) 14(-1.8,-3.075) 15(-1.4,-3.075) 16(-1,-3.075) 17(-0.6,-3.075) 18(-0.2,-3.075) 19(0.2,-3.075) 20(0.6,-3.075) 21(1,-3.075) 22(1.4,-3.075) 23(1.8,-3.075) 24(2.2,-3.075) 37(2.2,3.075) 38(1.8,3.075) 39(1.4,3.075) 40(1,3.075) 41(0.6,3.075) 42(0.2,3.075) 43(-0.2,3.075) 44(-0.6,3.075) 45(-1,3.075) 46(-1.4,3.075) 47(-1.8,3.075) 48(-2.2,3.075)
  rect 4.05x4.05 smd: 49(-0.225,0.225)
unnamed#2
  round 1.016 smd: 1(0,0)
unnamed#3
  round 2.032 hole 2.032 unplated: (0,0)
USB-003A-4P-90D
  rect 1.321x1.321 hole 0.914: 1(-3.5,2.71)
  round 1.321 hole 0.914: 2(-1,2.71) 3(1,2.71) 4(3.5,2.71)
  round 2.946 hole 2.337: 5(-6.57,0) 6(6.57,0)
X2_SMD_3_2X1_5MM
  rrect 0.762x1.524 smd: 1(-1.524,0) 2(1.524,0)
X4-SMD-3_2X2_5X1_0MM
  rect 1.321x1.067 smd: 1(-1.15,-0.925) 2(1.15,-0.925) 3(1.15,0.925) 4(-1.15,0.925)

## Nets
DGND: C1.1 C2.1 C3.1 C4.1 C5.2 C6.2 C7.1 C8.1 C9.1 C10.1 C11.1 C12.1 C13.1 C14.1 C15.1 C16.2 C17.2 C18.2 C19.2 C20.2 C23.2 C24.2 C27.2 C28.2 C29.2 C30.2 C34.2 C35.2 C36.2 C37.2 C38.2 C39.1 C40.1 C41.2 C42.2 C43.2 C44.2 C45.2 C46.2 C47.2 C48.2 C49.2 C50.2 C51.2 C52.2 C53.2 C54.2 C55.1 C56.1 C57.1 C58.2 C59.2 C60.1 C61.1 C62.1 C63.2 C64.2 C65.2 C66.2 C67.2 C68.1 C69.1 C70.1 C71.1 C72.1 C73.1 C74.1 C75.1 C76.1 C77.2 C78.2 C79.2 C80.2 C81.2 C82.2 C83.2 C84.2 C85.2 C86.2 C87.2 C88.2 C89.2 C90.2 C91.2 C92.2 C94.2 C95.1 C96.1 C97.2 C98.2 C99.2 C100.2 C101.2 C102.2 C103.2 C104.2 C105.2 C106.2 C107.2 C108.2 C109.2 C110.2 C111.2 C112.2 C113.2 C114.2 C115.2 C116.2 C117.2 C118.1 C119.2 C120.2 C121.2 C122.1 C123.2 C124.2 C125.2 C126.1 C127.2 C128.2 C129.2 C130.2 C131.2 C132.2 C133.1 C134.2 C135.2 C136.2 C137.2 C138.2 C139.2 C140.2 C141.2 C142.2 C143.2 C144.2 C145.2 C146.2 C147.2 C152.2 C153.2 C154.2 C155.1 C158.2 C159.2 D6.1 D7.1 FB3.2 J1.1 P2.4 P2.8 P2.10 P2.12 P2.16 P2.20 P3.4 P4.5 P5.8 P8.1 P8.2 P9.1 P9.2 P9.43 P9.44 P9.45 P9.46 P10.6(VSS) P10.9 Q1.1 Q1.4 Q2.1 Q2.4 R10.2 R12.1 R22.1 R25.2 R29.1 R30.1 R49.1 R53.2 R54.1 R76.2 R77.2 R78.2 R79.2 R80.2 R81.2 R82.2 R83.2 R84.2 R85.2 R86.2 R87.2 R88.2 R89.2 R90.2 R91.2 R92.2 R93.2 R94.2 R95.2 R96.1 R99.1 R100.2 R115.2 R116.2 R117.2 R118.2 R130.1 R132.1 R135.2 R136.1 R144.2 R145.2 R146.1 R147.1 R164.2 R165.2 R170.2 R173.2 R175.2 R176.2 S1.1 S1.3 S2.2 S2.4(B2) S3.1 S3.3 TP1.1(TP) TP8.1(TP) U1.3 U2.30 U2.41 U2.49 U3.3 U4.5 U4.6 U4.7 U4.8 U5.A1 U5.A18 U5.F8 U5.G8 U5.G9 U5.G11 U5.G12 U5.H6 U5.H7 U5.H8 U5.H9 U5.H10 U5.H12 U5.J6 U5.J7 U5.J8 U5.J9 U5.J10 U5.J11 U5.K7 U5.K9 U5.K10 U5.K11 U5.L10 U5.L11 U5.L12 U5.L13 U5.M6 U5.M7 U5.M8 U5.M9 U5.M10 U5.M12 U5.M14(VSSA_USB2) U5.N7 U5.N10 U5.N11 U5.N14 U5.V1 U5.V18 U6.3 U7.2 U8.1 U8.9(PAD) U9.4 U10.4 U12.A9 U12.B1 U12.B3 U12.B9 U12.D1 U12.D8 U12.E1 U12.E2 U12.E8 U12.F9 U12.G1 U12.G8 U12.G9 U12.J2 U12.J8 U12.M1 U12.M9 U12.P1 U12.P9 U12.T1 U12.T9 U13.A6 U13.C4(VSSQ4) U13.E7 U13.G5 U13.H10 U13.J5 U13.K8 U13.N2 U13.N5 U13.P4 U13.P6 U14.33 U15.1 U15.4 U16.3 Y3.2 Y3.4 Y4.2
GND_EARTH: C147.1 MTG1.1(TP) MTG2.1(TP) MTG3.1(TP) MTG4.1(TP) P3.5(SHELD1) P3.6 P4.6 P4.7 P4.8 P4.9 P5.13 P5.14 P10.S1 P10.S3 P10.S4 R136.2
GND_OSC0: C25.2 C26.2 R29.2 U5.V11 Y2.2 Y2.4
GND_OSC1: C21.1 C22.1 R30.2 U5.A5
GNDA_ADC: C31.2 C32.2 C33.2 C93.2 FB3.1 P9.34 U5.A9 U5.E8
VBUS: FB7.2 P3.1
VDD_1V8: C14.2 C78.1 C86.1 C88.1 FB1.1 FB2.2 R9.2 U2.40 U5.D10 U5.E9 U5.N16 U5.R16
VDD_3V3A: C15.2 C37.1 C38.1 C56.2 C57.2 C58.1 C59.1 C60.2 C61.2 C66.1 C67.1 C68.2 C69.2 C70.2 C71.2 C72.2 C73.2 C74.2 C75.2 C76.2 C77.1 C87.1 C152.1 C158.1 C159.1 R1.1 R3.1 R4.1 R14.1 R52.1 R55.1 R56.1 R57.1 R58.1 R59.1 R60.1 R61.1 R62.1 R63.1 R64.1 R65.1 R66.1 R67.1 R68.1 R69.1 R70.1 R156.1 R169.2 U2.43 U3.5 U4.1 U5.E10 U5.E11 U5.E12 U5.E13 U5.F14 U5.G14 U5.H14 U5.J14 U5.K14 U5.L14 U5.N5 U5.N15 U5.P5 U5.P6 U5.P7 U5.P8 U5.P10 U5.P11 U5.P12 U5.P13 U5.R15 U7.4 Y4.4(VCC)
VDD_3V3AUX: C18.1 D1.2 U2.1
VDD_3V3B: C20.1 C23.1 C29.1 C126.2 C127.1 C128.1 C129.1 C130.1 C135.1 C144.1 C153.1 C154.1 C155.2 FB4.1 J4.3 J5.3 P2.5(TVDD) P9.3 P9.4 P10.4 R11.1 R23.1 R24.1 R34.1 R35.1 R101.1 R102.1 R103.1 R104.1 R105.1 R106.1 R107.1 R108.1 R109.1 R110.1 R111.1 R112.2 R113.2 R114.2 R119.1 R150.1 R151.1 R152.1 R153.1 R154.1 R155.1 R157.2 R163.1 R177.1 R178.1 U1.5 U4.3(OUT) U6.5 U13.C6 U13.E6 U13.F5 U13.J10 U13.K9 U13.M4 U13.N4 U13.P3 U13.P5 U14.12 U15.7 U15.8(VCC)
VDD_5V: C2.2 P9.5 P9.6 R168.2 U2.10
VDD_ADC: C93.1 FB2.1 P9.32 R27.1 U5.D8
VDD_CORE: C11.2 C39.2 C40.2 C41.1 C42.1 C43.1 C44.1 C45.1 C46.1 C47.1 C48.1 C49.1 C50.1 C51.1 C52.1 C53.1 C54.1 C55.2 L3.2 U2.29 U5.F6 U5.F7 U5.G6 U5.G7 U5.G10 U5.H11 U5.J12 U5.K6 U5.K8 U5.K12 U5.L6 U5.L7 U5.L8 U5.L9 U5.M11 U5.M13 U5.N8 U5.N9 U5.N12 U5.N13
VDD_MPU: C12.2 C62.2 C63.1 C64.1 C65.1 L2.2 U2.24 U5.F10 U5.F11 U5.F12 U5.F13 U5.G13 U5.H13 U5.J13
VDD_MPUON: TP2.1(TP) U5.A2
VDD_PHYA: C131.1 C132.1 C133.2 FB4.2 R120.2 R121.2 R122.2 R123.2 R137.2 U14.1 U14.27
VDD_PLL: C79.1 C92.1 C94.1 C106.1 FB1.2 U5.E7 U5.H15 U5.R10 U5.R11
VDD_RTC: C104.1 U5.D6
VDDS: C80.1 C81.1 C82.1 C83.1 C84.1 C85.1 R8.2 R9.1 U5.E6 U5.E14 U5.F9 U5.K13 U5.N6 U5.P9 U5.P14
VDDS_DDR: C9.2 C95.2 C96.2 C97.1 C98.1 C99.1 C100.1 C101.1 C102.1 C103.1 C107.1 C108.1 C109.1 C110.1 C111.1 C112.1 C113.1 C114.1 C115.1 C116.1 C117.1 C118.2 C119.1 C120.1 C121.1 C122.2 R6.2 R97.1 R98.1 U5.E5 U5.F5 U5.G5 U5.H5 U5.J5 U5.K5 U5.L5 U12.A1 U12.A8 U12.B2 U12.C1 U12.C9 U12.D2 U12.D9 U12.E9 U12.F1 U12.G7 U12.H2 U12.H9 U12.K2 U12.K8 U12.N1 U12.N9 U12.R1 U12.R9
AIN0: P9.39 U5.B6
AIN1: P9.40 U5.C7
AIN2: P9.37 U5.B7
AIN3: P9.38 U5.A7
AIN4: P9.33 U5.C8
AIN5: P9.36 U5.B8
AIN6: P9.35 U5.A8
AIN7: R163.2 R164.1 U5.C9
AM3_MMC1_DAT0: R37.1 U5.U7
AM3_MMC1_DAT1: R38.1 U5.V7
AM3_MMC1_DAT2: R39.1 U5.R8
AM3_MMC1_DAT3: R40.1 U5.T8
AM3_MMC1_DAT4: R41.1 U5.U8
AM3_MMC1_DAT5: R42.1 U5.V8
AM3_MMC1_DAT6: R43.1 U5.R9
AM3_MMC1_DAT7: R44.1 U5.T9
B_UART0_RX: J1.4 R165.1 U15.2
B_UART0_TX: J1.5 U15.3
CAP_VBB_MPU: C91.1 U5.C10
CAP_VDD_SRAM_CORE: C89.1 U5.D9
CAP_VDD_SRAM_MPU: C90.1 U5.D11
CLKOUT2: P2.18 P9.41 R19.2 R20.1
CLKOUT_SRC: R19.1 U5.D14
CRS: R139.2 U14.14
DDR_A0: U5.F3 U12.N3
DDR_A1: U5.H1 U12.P7
DDR_A2: U5.E4 U12.P3
DDR_A3: U5.C3 U12.N2
DDR_A4: U5.C2 U12.P8
DDR_A5: U5.B1 U12.P2
DDR_A6: U5.D5 U12.R8
DDR_A7: U5.E2 U12.R2
DDR_A8: U5.D4 U12.T8
DDR_A9: U5.C1 U12.R3
DDR_A10: U5.F4 U12.L7
DDR_A11: U5.F2 U12.R7
DDR_A12: U5.E3 U12.N7
DDR_A13: U5.H3 U12.T3
DDR_A14: U5.H4 U12.T7
DDR_A15: U5.D3 U12.M7
DDR_BA0: U5.C4 U12.M2
DDR_BA1: U5.E1 U12.N8
DDR_BA2: U5.B3 U12.M3
DDR_CASN: U5.F1 U12.K3
DDR_CKE: R96.2 U5.G3 U12.K9
DDR_CLK: U5.D2 U12.J7
DDR_CLKN: U5.D1 U12.K7
DDR_CSN: U5.H2 U12.L2
DDR_D0: U5.M3 U12.E3
DDR_D1: U5.M4 U12.F7
DDR_D2: U5.N1 U12.F2
DDR_D3: U5.N2 U12.F8
DDR_D4: U5.N3 U12.H3
DDR_D5: U5.N4 U12.H8
DDR_D6: U5.P3 U12.G2
DDR_D7: U5.P4 U12.H7
DDR_D8: U5.J1 U12.D7
DDR_D9: U5.K1 U12.C3
DDR_D10: U5.K2 U12.C8
DDR_D11: U5.K3 U12.C2
DDR_D12: U5.K4 U12.A7
DDR_D13: U5.L3 U12.A2
DDR_D14: U5.L4 U12.B8
DDR_D15: U5.M1 U12.A3
DDR_DQM0: U5.M2 U12.E7
DDR_DQM1: U5.J2 U12.D3
DDR_DQS0: U5.P1 U12.F3
DDR_DQS1: U5.L1 U12.C7
DDR_DQSN0: U5.P2 U12.G3
DDR_DQSN1: U5.L2 U12.B7
DDR_ODT: U5.G1 U12.K1
DDR_RASN: U5.G4 U12.J3
DDR_RESETN: R97.2 U5.G2 U12.T2
DDR_VREF: C28.1 C123.1 C124.1 R98.2 R100.1 U5.J4 U12.H1 U12.M8
DDR_VTP: R22.2 U5.J3
DDR_WEN: U5.B2 U12.L3
EHRPWM1A: P9.14 U5.U14
EHRPWM1B: P9.16 U5.T14
EHRPWM2A: P8.19 U5.U10
EHRPWM2B: P8.13 U5.T10
EMMC_RSTN: R111.2 R162.2 U13.K5
EMMC_VCCI: C125.1 U13.C2
ENZ_KALDO_1P8V: R54.2 U5.B4
ETH_RESETN: C27.1 R35.2 U1.4(Y) U14.19
ETH_RST_GPIO1_8: R34.2 U1.1 U5.E18
ETH_TXD4: R145.1 U14.18
GPIO0_7: P9.42 R50.1 R51.1
GPIO0_7SRC: R50.2 U5.C18
GPIO0_26: P8.14 U5.T11
GPIO0_27: P8.17(9) U5.U12
GPIO1_12: P8.12 U5.T12
GPIO1_13: P8.11 U5.R12
GPIO1_14: P8.16 U5.V13
GPIO1_15: P8.15 U5.U13
GPIO1_16: P9.15 R160.2 R161.2
GPIO1_17: P9.23 U5.V14
GPIO1_28: P9.12 U5.U18
GPIO1_29: P8.26 U5.V6
GPIO2_1: P8.18 U5.V12
GPIO3_18: R51.2 U5.B12
GPIO3_19: P9.27 U5.C13
GPIO3_20: R20.2 U5.D13
GPIO3_21: P9.25 R167.2 U5.A14
GRN_C: P5.10 R132.2
GRNA: P5.9 U14.3
HDMI_INT: R169.1 R170.1 U5.U16
HDMICLK_DISN: U5.V17 Y4.1
I2C0_SCL: R3.2 U2.28 U5.C16 U7.1
I2C0_SDA: R4.2 U2.27 U5.C17 U7.3
I2C1_SCL: P9.17(9) U5.A16
I2C1_SDA: P9.18 U5.B16
I2C2_SCL: J4.1 P9.19 R177.2 U5.D17
I2C2_SDA: J4.2 P9.20 R178.2 U5.D18
JTAG_EMU0: P2.13 R23.2 U5.C14
JTAG_EMU1: P2.14 R24.2 U5.B14
JTAG_TCK: P2.9 P2.11 U5.A12
JTAG_TDI: P2.3 U5.B11
JTAG_TDO: P2.7 U5.A11
JTAG_TMS: P2.1 U5.C11
JTAG_TRSTN: P2.2 R25.1 U5.B10
LCD_DATA0: P8.45 R70.2 R95.1 U5.R1
LCD_DATA1: P8.46 R69.2 R94.1 U5.R2
LCD_DATA2: P8.43 R68.2 R75.1 R93.1 U5.R3
LCD_DATA3: P8.44 R67.2 R92.1 U5.R4
LCD_DATA4: P8.41 R66.2 R91.1 U5.T1
LCD_DATA5: P8.42 R65.2 R90.1 U5.T2
LCD_DATA6: P8.39 R64.2 R89.1 U5.T3
LCD_DATA7: P8.40 R63.2 R88.1 U5.T4
LCD_DATA8: P8.37 R62.2 R87.1 U5.U1
LCD_DATA9: P8.38 R61.2 R86.1 U5.U2
LCD_DATA10: P8.36 R60.2 R85.1 U5.U3
LCD_DATA11: P8.34 R59.2 R84.1 U5.U4
LCD_DATA12: P8.35 R58.2 R83.1 U5.V2
LCD_DATA13: P8.33 R57.2 R82.1 U5.V3
LCD_DATA14: P8.31 R56.2 R81.1 U5.V4
LCD_DATA15: P8.32 R55.2 R80.1 U5.T5
LCD_DE: P8.30 R48.2
LCD_HSYNC: P8.29 R47.2
LCD_PCLK: P8.28 R45.2
LCD_VSYNC: P8.27 R46.2
LCDDE: R48.1 U5.R6
LCDPCLK: R45.1 U5.V5
LCDVHYNC: R47.1 U5.R5
LCDVSYNC: R46.1 U5.U5
LDO_PGOOD: U2.46 U5.B5
LEDAA: D2.2 R72.2
LEDAC: D2.1(C) Q1.6
LEDBA: D3.2 R73.2
LEDBC: D3.1(C) Q1.3
LEDCA: D4.2 R74.2
LEDCC: D4.1(C) Q2.6
LEDDA: D5.2 R71.2
LEDDC: D5.1(C) Q2.3
MDIO_CLK: U5.M18 U14.17
MDIO_DATA: R119.2 U5.M17 U14.16
MII1_COL: R138.1 U5.H16
MII1_CRS_DV: R139.1 U5.H17
MII1_REFCLK: R28.2 R124.1 R140.1
MII1_RXCLK: R131.1 U5.L18
MII1_RXD0: R128.1 U5.M16
MII1_RXD1: R127.1 U5.L15
MII1_RXD2: R126.1 U5.L16
MII1_RXD3: R125.1 U5.L17
MII1_RXDV: R129.1 U5.J17
MII1_RXERR: R133.1 U5.J15
MII1_TXCLK: R134.1 U5.K18
MII1_TXD0: R158.1 U5.K17
MII1_TXD1: R166.1 U5.K16
MII1_TXD2: R171.1 U5.K15
MII1_TXD3: R172.1 U5.J18
MII1_TXEN: R149.1 U5.J16
MMC0_CD: P2.19 P10.10 R157.1 U5.C15
MMC0_CLKO: R16.1 U5.G17
MMC0_CMD: R15.1 U5.G18
MMC0_DAT0: R21.1 U5.G16
MMC0_DAT1: R31.1 U5.G15
MMC0_DAT2: R2.1 U5.F18
MMC0_DAT3: R13.1 U5.F17
MMC1_CLK: C6.1 P8.21 R32.2 R110.2 U13.M6
MMC1_CMD: P8.20 R33.2 R109.2 U13.M5
MMC1_DAT0: P8.25 R37.2 R101.2 U13.A3
MMC1_DAT1: P8.24 R38.2 R102.2 U13.A4
MMC1_DAT2: P8.5 R39.2 R103.2 U13.A5
MMC1_DAT3: P8.6 R40.2 R104.2 U13.B2
MMC1_DAT4: P8.23 R41.2 R105.2 U13.B3
MMC1_DAT5: P8.22 R42.2 R106.2 U13.B4
MMC1_DAT6: P8.3 R43.2 R107.2 U13.B5
MMC1_DAT7: P8.4 R44.2 R108.2 U13.B6
MODE2: R113.1 R138.2 U14.15
OSC0_IN: C25.1 R17.1 U5.V10 Y2.1
OSC0_OUT: R17.2 R179.1 U5.U11
OSC1_IN: C21.2 U5.A6 Y1.2
OSC1_OUT: C22.2 U5.A4 Y1.1
P_BYPASS: C4.2 U2.47
P_INT_LDO: C3.2 U2.48
P_L1: L1.1 U2.20
P_L2: L2.1 U2.23
P_L3: L3.1 U2.31
PHY_VDDCR: C134.1 C136.1 U14.6
PHY_XTAL1: C143.1 R141.2 R142.1 Y3.3
PHY_XTAL2: R141.1 R143.2 U14.4(XTAL2)
PHYX: C142.1 R143.1 Y3.1
PMIC_INT: R1.2 U2.45 U5.B18
PMIC_PGOOD: U2.26 U5.B15 U16.2
PMIC_POWR_EN: U2.9 U5.C6
PROC_A15: R18.1 U5.A15
PWR_BUT: P9.9 S3.2 S3.4(B2) U2.25
PWR_LEDR: D1.1(C) R12.2
RBIAS: R144.1 U14.32
RCLKIN: R140.2 R142.2 U14.5
REFCLKO: R118.1 R124.2 R131.2 U14.7
RXD0/MODE0: R112.1 R128.2 U14.11
RXD1/MODE1: R114.1 R127.2 U14.10
RXD2/RMIISEL: R117.1 R126.2 U14.9
RXD3/PHYAD2: R116.1 R125.2 U14.8
RXDV: R129.2 U14.26
RXER/PHYAD0: R115.1 R133.2 U14.13
RXN: C138.1 P5.2 R121.1 U14.30
RXP: C137.1 P5.1 R120.1 U14.31
SD_CLK: C5.1 P10.5 R16.2 R152.2
SD_CMD: P10.3 R15.2 R151.2
SD_DAT0: P10.7 R21.2 R153.2
SD_DAT1: P10.8 R31.2 R154.2
SD_DAT2: P10.1 R2.2 R150.2
SD_DAT3: P10.2 R13.2 R155.2
SPI1_CS0: P9.28 U5.C12
SPI1_D0: P9.29 U5.B13
SPI1_D1: P9.30 U5.D12
SPI1_SCLK: P9.31 U5.A13
SYS_5V: C7.2 C8.2 C10.2 C13.2 C17.1 C34.1 P9.7 P9.8 R71.1 R72.1 R73.1 R74.1 U2.2 U2.7 U2.8 U2.21 U2.22 U2.32 U2.39 U2.42 U4.2 U8.2 U8.3
SYS_RESETN: C24.1 C30.1 D6.2 D7.2 P2.15 P9.10 R14.2 R148.1 S1.2 S1.4(B2) U5.A10 U6.2 U16.4(Y)
TCT_RCT: C141.1 P5.4 P5.5 R137.1
TESTOUT: TP3.1(TP) U5.A3
TIMER4: P8.7 U5.R7
TIMER5: P8.9 U5.T6
TIMER6: P8.10 U5.U6
TIMER7: P8.8 U5.T7
TXCLK: R134.2 U14.20
TXD0: R158.2 U14.22
TXD1: R166.2 U14.23
TXD2: R171.2 U14.24
TXD3: R172.2 U14.25
TXEN: R149.2 U14.21
TXN: C140.1 P5.6 R123.1 U14.28
TXP: C139.1 P5.3 R122.1 U14.29
U5_H18: R28.1 U5.H18
U5_R13: R160.1 U5.R13
U5_T13: R161.1 U5.T13
UART0_RX: U5.E15 U15.6
UART0_TX: U5.E16 U15.5
UART1_RXD: P9.26 U5.D16
UART1_TXD: P9.24 U5.D15
UART2_RXD: J5.1 P9.22 U5.A17
UART2_TXD: J5.2 P9.21 U5.B17
UART4_RXD: P9.11 U5.T17
UART4_TXD: P9.13 U5.U17
USB0_DM: P4.2 U5.N18 U10.2
USB0_DP: P4.3 U5.N17 U10.1
USB0_ID: P4.4 U5.P16 U10.3
USB1_DM: P3.2 U5.R18 U9.2
USB1_DP: P3.3 U5.R17 U9.1
USB1_DRVVBUS: R53.1 U5.F15 U8.4
USB1_ID: R49.2 U5.P17
USB1_OCN: R52.2 U5.T16 U8.5
USB1_PWR: C35.1 FB7.1 R36.2 U8.6 U8.7 U8.8 U9.6(VBUS)
USB1_VBUS: R36.1 U5.T18
USB_DC: C1.2 C36.1 P4.1(VB) R159.1 R168.1 U2.12 U10.6(VBUS)
USR0: Q1.2 R76.1 U5.V15
USR1: Q1.5 R77.1 U5.U15
USR2: Q2.2 R78.1 U5.T15
USR3: Q2.5 R79.1 U5.V16
VDCDC1: L1.2 R6.1 U2.19
VIO: C146.1 R7.2 U2.18 U16.5
VLDO1: R5.1 R7.1 R8.1 U2.3
VREFP_ADC: C31.1 C32.1 C33.1 R27.2 U5.B9
VRTC: C16.1 C105.1 R5.2 R26.1 U5.D7
WAKEUP: R26.2 U2.13(WAKEUP) U5.C5
WP: R156.2 TP4.1(TP) U7.5(WP)
XDMA_EVENT_INTR0: P2.17 R18.2
YEL_C: P5.11(YELC) R130.2
YELA: P5.12 R135.1 U14.2
ZQ: R99.2 U12.L8(ZQ)
N21757673: C19.1 R10.1 R11.2 U4.4
N21769115: R75.2 S2.1 S2.3
N22155575: R159.2 U5.P15
N22248684: R167.1 Y4.3
N22287501: R162.1 U3.4(Y)
N22287555: U3.2 U5.R14
N22420400: R173.1 R174.2 TP5.1(TP) U2.4 U2.5
N22420444: R174.1 TP6.1(TP) U2.6
N22420447: TP7.1(TP) U2.11
N22488252: TP9.1(TP) U5.E17
N22569088: J5.4 R147.2
N22569092: J4.4 R146.2
N22710186: R32.1 U5.U9
N22710189: R33.1 U5.V9
N22740401: C145.1 R148.2 U1.2 U6.4(Y)
N22823317: R175.1 U2.33
N22823323: R176.1 U2.34
N22872429: C26.1 R179.2 Y2.3
